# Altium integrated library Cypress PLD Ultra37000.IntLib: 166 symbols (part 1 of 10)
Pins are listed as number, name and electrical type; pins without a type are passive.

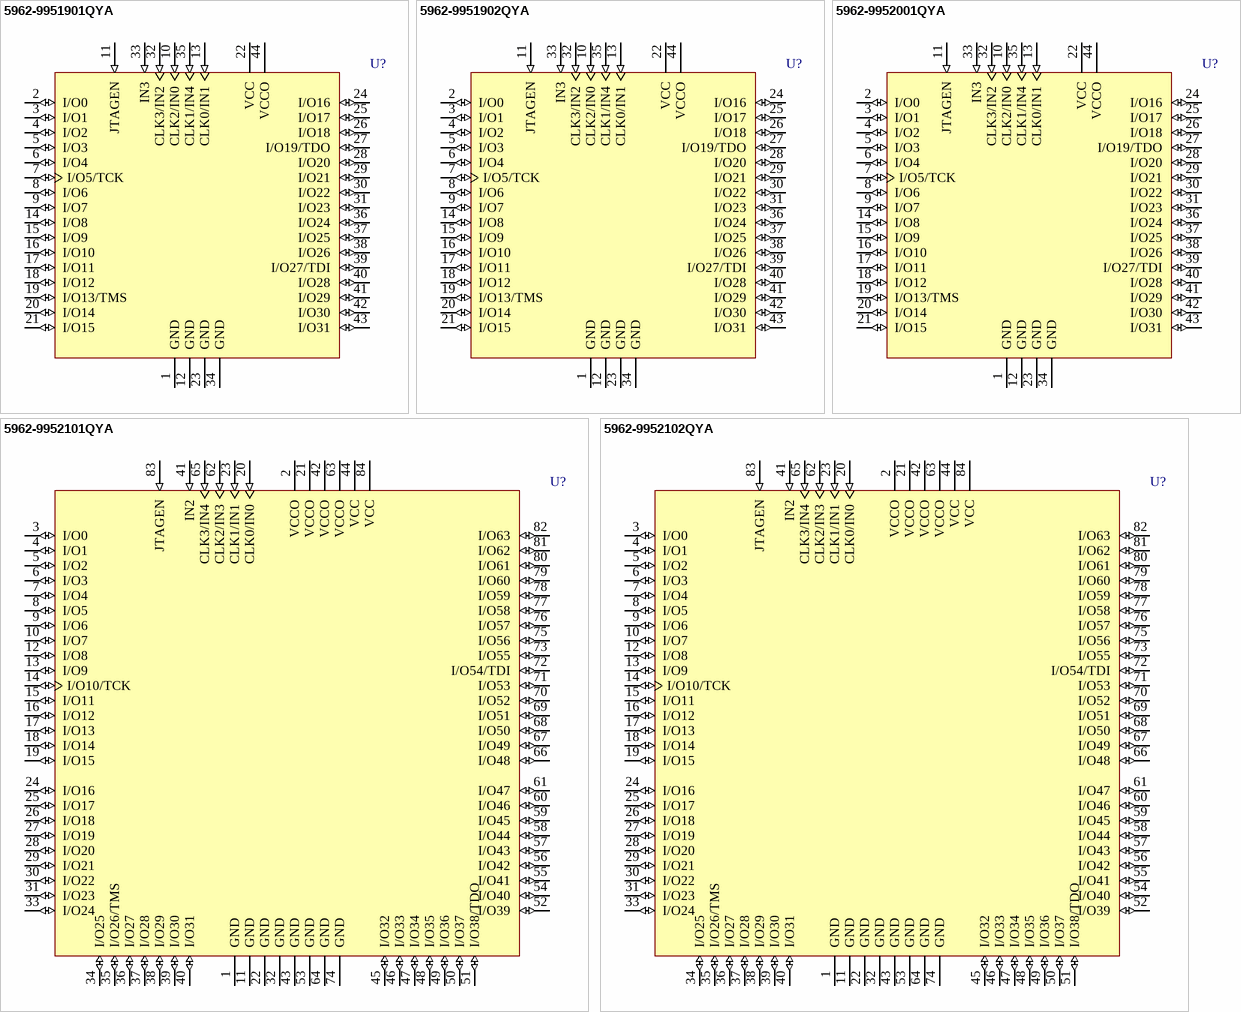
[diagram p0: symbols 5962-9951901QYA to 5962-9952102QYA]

## 5962-9951901QYA
designator U?
Ultra37000 5V, ISR High-Performance CPLD; Note: Component Name corresponds to Military Range
footprint Y67_N (Leaded Chip Carrier, 44-Leads, Body 16.5x16.5mm, Pitch 1.27mm, IPC Medium Density)
footprint Y67_L (Leaded Chip Carrier, 44-Leads, Body 16.5x16.5mm, Pitch 1.27mm, IPC High Density)
footprint Y67_M (Leaded Chip Carrier, 44-Leads, Body 16.5x16.5mm, Pitch 1.27mm, IPC Low Density)
3D model Y67 (44-Pin Ceramic Leaded Chip Carrier 1.27 mm Pitch)
pins: 1 GND (power), 2 I/O0 (io), 3 I/O1 (io), 4 I/O2 (io), 5 I/O3 (io), 6 I/O4 (io), 7 I/O5/TCK (io), 8 I/O6 (io), 9 I/O7 (io), 10 CLK2/IN0 (in), 11 JTAGEN (in), 12 GND (power), 13 CLK0/IN1 (in), 14 I/O8 (io), 15 I/O9 (io), 16 I/O10 (io), 17 I/O11 (io), 18 I/O12 (io), 19 I/O13/TMS (io), 20 I/O14 (io), 21 I/O15 (io), 22 VCC (power), 23 GND (power), 24 I/O16 (io), 25 I/O17 (io), 26 I/O18 (io), 27 I/O19/TDO (io), 28 I/O20 (io), 29 I/O21 (io), 30 I/O22 (io), 31 I/O23 (io), 32 CLK3/IN2 (in), 33 IN3 (in), 34 GND (power), 35 CLK1/IN4 (in), 36 I/O24 (io), 37 I/O25 (io), 38 I/O26 (io), 39 I/O27/TDI (io), 40 I/O28 (io), 41 I/O29 (io), 42 I/O30 (io), 43 I/O31 (io), 44 VCCO (power)

## 5962-9951902QYA
designator U?
Ultra37000 5V, ISR High-Performance CPLD; Note: Component Name corresponds to Military Range
footprint Y67_N (Leaded Chip Carrier, 44-Leads, Body 16.5x16.5mm, Pitch 1.27mm, IPC Medium Density)
footprint Y67_L (Leaded Chip Carrier, 44-Leads, Body 16.5x16.5mm, Pitch 1.27mm, IPC High Density)
footprint Y67_M (Leaded Chip Carrier, 44-Leads, Body 16.5x16.5mm, Pitch 1.27mm, IPC Low Density)
3D model Y67 (44-Pin Ceramic Leaded Chip Carrier 1.27 mm Pitch)
pins: 1 GND (power), 2 I/O0 (io), 3 I/O1 (io), 4 I/O2 (io), 5 I/O3 (io), 6 I/O4 (io), 7 I/O5/TCK (io), 8 I/O6 (io), 9 I/O7 (io), 10 CLK2/IN0 (in), 11 JTAGEN (in), 12 GND (power), 13 CLK0/IN1 (in), 14 I/O8 (io), 15 I/O9 (io), 16 I/O10 (io), 17 I/O11 (io), 18 I/O12 (io), 19 I/O13/TMS (io), 20 I/O14 (io), 21 I/O15 (io), 22 VCC (power), 23 GND (power), 24 I/O16 (io), 25 I/O17 (io), 26 I/O18 (io), 27 I/O19/TDO (io), 28 I/O20 (io), 29 I/O21 (io), 30 I/O22 (io), 31 I/O23 (io), 32 CLK3/IN2 (in), 33 IN3 (in), 34 GND (power), 35 CLK1/IN4 (in), 36 I/O24 (io), 37 I/O25 (io), 38 I/O26 (io), 39 I/O27/TDI (io), 40 I/O28 (io), 41 I/O29 (io), 42 I/O30 (io), 43 I/O31 (io), 44 VCCO (power)

## 5962-9952001QYA
designator U?
Ultra37000 3.3V, ISR High-Performance CPLD; Note: Component Name corresponds to Military Range
footprint Y67_N (Leaded Chip Carrier, 44-Leads, Body 16.5x16.5mm, Pitch 1.27mm, IPC Medium Density)
footprint Y67_L (Leaded Chip Carrier, 44-Leads, Body 16.5x16.5mm, Pitch 1.27mm, IPC High Density)
footprint Y67_M (Leaded Chip Carrier, 44-Leads, Body 16.5x16.5mm, Pitch 1.27mm, IPC Low Density)
3D model Y67 (44-Pin Ceramic Leaded Chip Carrier 1.27 mm Pitch)
pins: 1 GND (power), 2 I/O0 (io), 3 I/O1 (io), 4 I/O2 (io), 5 I/O3 (io), 6 I/O4 (io), 7 I/O5/TCK (io), 8 I/O6 (io), 9 I/O7 (io), 10 CLK2/IN0 (in), 11 JTAGEN (in), 12 GND (power), 13 CLK0/IN1 (in), 14 I/O8 (io), 15 I/O9 (io), 16 I/O10 (io), 17 I/O11 (io), 18 I/O12 (io), 19 I/O13/TMS (io), 20 I/O14 (io), 21 I/O15 (io), 22 VCC (power), 23 GND (power), 24 I/O16 (io), 25 I/O17 (io), 26 I/O18 (io), 27 I/O19/TDO (io), 28 I/O20 (io), 29 I/O21 (io), 30 I/O22 (io), 31 I/O23 (io), 32 CLK3/IN2 (in), 33 IN3 (in), 34 GND (power), 35 CLK1/IN4 (in), 36 I/O24 (io), 37 I/O25 (io), 38 I/O26 (io), 39 I/O27/TDI (io), 40 I/O28 (io), 41 I/O29 (io), 42 I/O30 (io), 43 I/O31 (io), 44 VCCO (power)

## 5962-9952101QYA
designator U?
Ultra37000 5V, ISR High-Performance CPLD; Note: Component Name corresponds to Military Range
footprint Y84_N (Leaded Chip Carrier, 84-Leads, Body 29.2x29.2mm, Pitch 1.27mm, IPC Medium Density)
footprint Y84_L (Leaded Chip Carrier, 84-Leads, Body 29.2x29.2mm, Pitch 1.27mm, IPC High Density)
footprint Y84_M (Leaded Chip Carrier, 84-Leads, Body 29.2x29.2mm, Pitch 1.27mm, IPC Low Density)
3D model Y84 (84-Pin Ceramic Leaded Chip Carrier 1.27 mm Pitch)
pins: 1 GND (power), 2 VCCO (power), 3 I/O0 (io), 4 I/O1 (io), 5 I/O2 (io), 6 I/O3 (io), 7 I/O4 (io), 8 I/O5 (io), 9 I/O6 (io), 10 I/O7 (io), 11 GND (power), 12 I/O8 (io), 13 I/O9 (io), 14 I/O10/TCK (io), 15 I/O11 (io), 16 I/O12 (io), 17 I/O13 (io), 18 I/O14 (io), 19 I/O15 (io), 20 CLK0/IN0 (in), 21 VCCO (power), 22 GND (power), 23 CLK1/IN1 (in), 24 I/O16 (io), 25 I/O17 (io), 26 I/O18 (io), 27 I/O19 (io), 28 I/O20 (io), 29 I/O21 (io), 30 I/O22 (io), 31 I/O23 (io), 32 GND (power), 33 I/O24 (io), 34 I/O25 (io), 35 I/O26/TMS (io), 36 I/O27 (io), 37 I/O28 (io), 38 I/O29 (io), 39 I/O30 (io), 40 I/O31 (io), 41 IN2 (in), 42 VCCO (power), 43 GND (power), 44 VCC (power), 45 I/O32 (io), 46 I/O33 (io), 47 I/O34 (io), 48 I/O35 (io), 49 I/O36 (io), 50 I/O37 (io), 51 I/O38/TDO (io), 52 I/O39 (io), 53 GND (power), 54 I/O40 (io), 55 I/O41 (io), 56 I/O42 (io), 57 I/O43 (io), 58 I/O44 (io), 59 I/O45 (io), 60 I/O46 (io), 61 I/O47 (io), 62 CLK2/IN3 (in), 63 VCCO (power), 64 GND (power), 65 CLK3/IN4 (in), 66 I/O48 (io), 67 I/O49 (io), 68 I/O50 (io), 69 I/O51 (io), 70 I/O52 (io), 71 I/O53 (io), 72 I/O54/TDI (io), 73 I/O55 (io), 74 GND (power), 75 I/O56 (io), 76 I/O57 (io), 77 I/O58 (io), 78 I/O59 (io), 79 I/O60 (io), 80 I/O61 (io), 81 I/O62 (io), 82 I/O63 (io), 83 JTAGEN (in), 84 VCC (power)

## 5962-9952102QYA
designator U?
Ultra37000 5V, ISR High-Performance CPLD; Note: Component Name corresponds to Military Range
footprint Y84_N (Leaded Chip Carrier, 84-Leads, Body 29.2x29.2mm, Pitch 1.27mm, IPC Medium Density)
footprint Y84_L (Leaded Chip Carrier, 84-Leads, Body 29.2x29.2mm, Pitch 1.27mm, IPC High Density)
footprint Y84_M (Leaded Chip Carrier, 84-Leads, Body 29.2x29.2mm, Pitch 1.27mm, IPC Low Density)
3D model Y84 (84-Pin Ceramic Leaded Chip Carrier 1.27 mm Pitch)
pins: 1 GND (power), 2 VCCO (power), 3 I/O0 (io), 4 I/O1 (io), 5 I/O2 (io), 6 I/O3 (io), 7 I/O4 (io), 8 I/O5 (io), 9 I/O6 (io), 10 I/O7 (io), 11 GND (power), 12 I/O8 (io), 13 I/O9 (io), 14 I/O10/TCK (io), 15 I/O11 (io), 16 I/O12 (io), 17 I/O13 (io), 18 I/O14 (io), 19 I/O15 (io), 20 CLK0/IN0 (in), 21 VCCO (power), 22 GND (power), 23 CLK1/IN1 (in), 24 I/O16 (io), 25 I/O17 (io), 26 I/O18 (io), 27 I/O19 (io), 28 I/O20 (io), 29 I/O21 (io), 30 I/O22 (io), 31 I/O23 (io), 32 GND (power), 33 I/O24 (io), 34 I/O25 (io), 35 I/O26/TMS (io), 36 I/O27 (io), 37 I/O28 (io), 38 I/O29 (io), 39 I/O30 (io), 40 I/O31 (io), 41 IN2 (in), 42 VCCO (power), 43 GND (power), 44 VCC (power), 45 I/O32 (io), 46 I/O33 (io), 47 I/O34 (io), 48 I/O35 (io), 49 I/O36 (io), 50 I/O37 (io), 51 I/O38/TDO (io), 52 I/O39 (io), 53 GND (power), 54 I/O40 (io), 55 I/O41 (io), 56 I/O42 (io), 57 I/O43 (io), 58 I/O44 (io), 59 I/O45 (io), 60 I/O46 (io), 61 I/O47 (io), 62 CLK2/IN3 (in), 63 VCCO (power), 64 GND (power), 65 CLK3/IN4 (in), 66 I/O48 (io), 67 I/O49 (io), 68 I/O50 (io), 69 I/O51 (io), 70 I/O52 (io), 71 I/O53 (io), 72 I/O54/TDI (io), 73 I/O55 (io), 74 GND (power), 75 I/O56 (io), 76 I/O57 (io), 77 I/O58 (io), 78 I/O59 (io), 79 I/O60 (io), 80 I/O61 (io), 81 I/O62 (io), 82 I/O63 (io), 83 JTAGEN (in), 84 VCC (power)

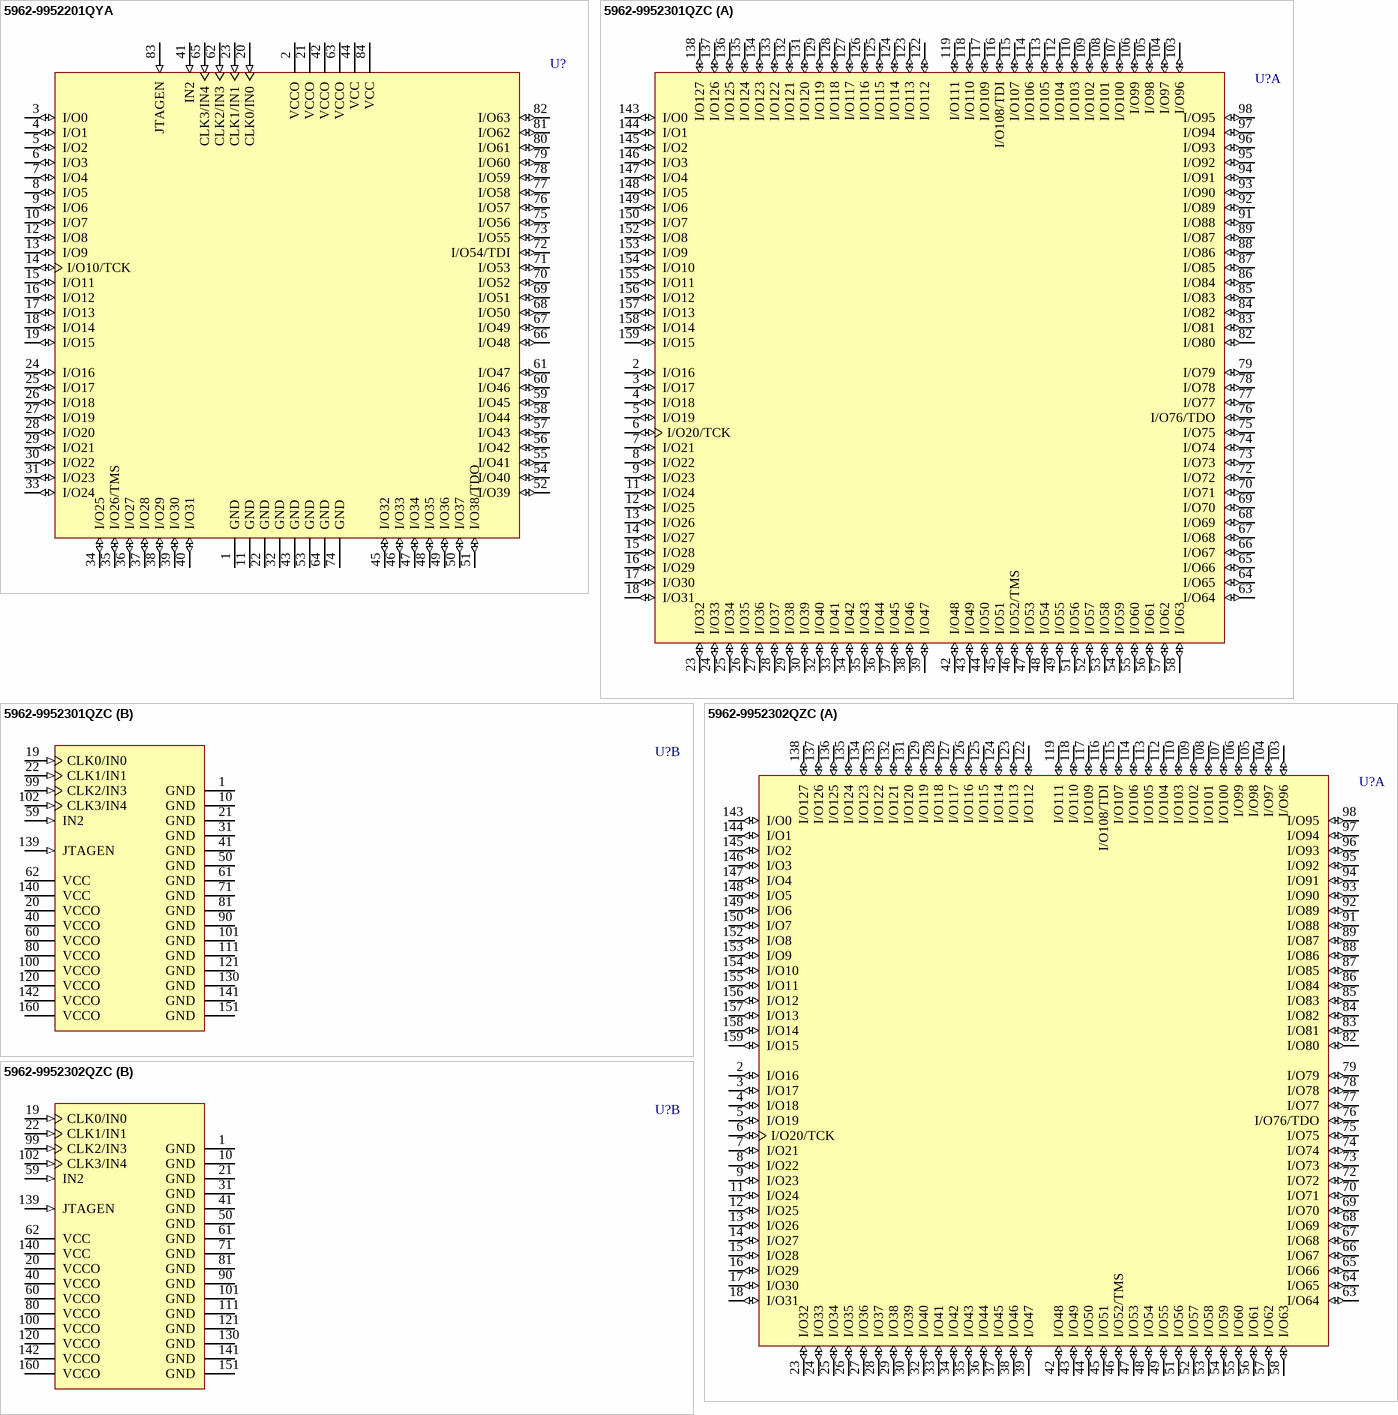
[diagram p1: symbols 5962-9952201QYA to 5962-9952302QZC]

## 5962-9952201QYA
designator U?
Ultra37000 3.3V, ISR High-Performance CPLD; Note: Component Name corresponds to Military Range
footprint Y84_N (Leaded Chip Carrier, 84-Leads, Body 29.2x29.2mm, Pitch 1.27mm, IPC Medium Density)
footprint Y84_L (Leaded Chip Carrier, 84-Leads, Body 29.2x29.2mm, Pitch 1.27mm, IPC High Density)
footprint Y84_M (Leaded Chip Carrier, 84-Leads, Body 29.2x29.2mm, Pitch 1.27mm, IPC Low Density)
3D model Y84 (84-Pin Ceramic Leaded Chip Carrier 1.27 mm Pitch)
pins: 1 GND (power), 2 VCCO (power), 3 I/O0 (io), 4 I/O1 (io), 5 I/O2 (io), 6 I/O3 (io), 7 I/O4 (io), 8 I/O5 (io), 9 I/O6 (io), 10 I/O7 (io), 11 GND (power), 12 I/O8 (io), 13 I/O9 (io), 14 I/O10/TCK (io), 15 I/O11 (io), 16 I/O12 (io), 17 I/O13 (io), 18 I/O14 (io), 19 I/O15 (io), 20 CLK0/IN0 (in), 21 VCCO (power), 22 GND (power), 23 CLK1/IN1 (in), 24 I/O16 (io), 25 I/O17 (io), 26 I/O18 (io), 27 I/O19 (io), 28 I/O20 (io), 29 I/O21 (io), 30 I/O22 (io), 31 I/O23 (io), 32 GND (power), 33 I/O24 (io), 34 I/O25 (io), 35 I/O26/TMS (io), 36 I/O27 (io), 37 I/O28 (io), 38 I/O29 (io), 39 I/O30 (io), 40 I/O31 (io), 41 IN2 (in), 42 VCCO (power), 43 GND (power), 44 VCC (power), 45 I/O32 (io), 46 I/O33 (io), 47 I/O34 (io), 48 I/O35 (io), 49 I/O36 (io), 50 I/O37 (io), 51 I/O38/TDO (io), 52 I/O39 (io), 53 GND (power), 54 I/O40 (io), 55 I/O41 (io), 56 I/O42 (io), 57 I/O43 (io), 58 I/O44 (io), 59 I/O45 (io), 60 I/O46 (io), 61 I/O47 (io), 62 CLK2/IN3 (in), 63 VCCO (power), 64 GND (power), 65 CLK3/IN4 (in), 66 I/O48 (io), 67 I/O49 (io), 68 I/O50 (io), 69 I/O51 (io), 70 I/O52 (io), 71 I/O53 (io), 72 I/O54/TDI (io), 73 I/O55 (io), 74 GND (power), 75 I/O56 (io), 76 I/O57 (io), 77 I/O58 (io), 78 I/O59 (io), 79 I/O60 (io), 80 I/O61 (io), 81 I/O62 (io), 82 I/O63 (io), 83 JTAGEN (in), 84 VCC (power)

## 5962-9952301QZC
designator U?
Ultra37000 5V, ISR High-Performance CPLD; Note: Component Name corresponds to Military Range
footprint U162_N (QFP, 160-Leads, Body 28 x 28mm, Pitch 0.65mm, IPC Medium Density)
footprint U162_L (QFP, 160-Leads, Body 28 x 28mm, Pitch 0.65mm, IPC High Density)
footprint U162_M (QFP, 160-Leads, Body 28 x 28mm, Pitch 0.65mm, IPC Low Density)
3D model U162 (160-Pin Ceramic Cavity Up Quad Flat Pack 0.65 mm Pitch)
part A pins: 2 I/O16 (io), 3 I/O17 (io), 4 I/O18 (io), 5 I/O19 (io), 6 I/O20/TCK (io), 7 I/O21 (io), 8 I/O22 (io), 9 I/O23 (io), 11 I/O24 (io), 12 I/O25 (io), 13 I/O26 (io), 14 I/O27 (io), 15 I/O28 (io), 16 I/O29 (io), 17 I/O30 (io), 18 I/O31 (io), 23 I/O32 (io), 24 I/O33 (io), 25 I/O34 (io), 26 I/O35 (io), 27 I/O36 (io), 28 I/O37 (io), 29 I/O38 (io), 30 I/O39 (io), 32 I/O40 (io), 33 I/O41 (io), 34 I/O42 (io), 35 I/O43 (io), 36 I/O44 (io), 37 I/O45 (io), 38 I/O46 (io), 39 I/O47 (io), 42 I/O48 (io), 43 I/O49 (io), 44 I/O50 (io), 45 I/O51 (io), 46 I/O52/TMS (io), 47 I/O53 (io), 48 I/O54 (io), 49 I/O55 (io), 51 I/O56 (io), 52 I/O57 (io), 53 I/O58 (io), 54 I/O59 (io), 55 I/O60 (io), 56 I/O61 (io), 57 I/O62 (io), 58 I/O63 (io), 63 I/O64 (io), 64 I/O65 (io), 65 I/O66 (io), 66 I/O67 (io), 67 I/O68 (io), 68 I/O69 (io), 69 I/O70 (io), 70 I/O71 (io), 72 I/O72 (io), 73 I/O73 (io), 74 I/O74 (io), 75 I/O75 (io), 76 I/O76/TDO (io), 77 I/O77 (io), 78 I/O78 (io), 79 I/O79 (io), 82 I/O80 (io), 83 I/O81 (io), 84 I/O82 (io), 85 I/O83 (io), 86 I/O84 (io), 87 I/O85 (io), 88 I/O86 (io), 89 I/O87 (io), 91 I/O88 (io), 92 I/O89 (io), 93 I/O90 (io), 94 I/O91 (io), 95 I/O92 (io), 96 I/O93 (io), 97 I/O94 (io), 98 I/O95 (io), 103 I/O96 (io), 104 I/O97 (io), 105 I/O98 (io), 106 I/O99 (io), 107 I/O100 (io), 108 I/O101 (io), 109 I/O102 (io), 110 I/O103 (io), 112 I/O104 (io), 113 I/O105 (io), 114 I/O106 (io), 115 I/O107 (io), 116 I/O108/TDI (io), 117 I/O109 (io), 118 I/O110 (io), 119 I/O111 (io), 122 I/O112 (io), 123 I/O113 (io), 124 I/O114 (io), 125 I/O115 (io), 126 I/O116 (io), 127 I/O117 (io), 128 I/O118 (io), 129 I/O119 (io), 131 I/O120 (io), 132 I/O121 (io), 133 I/O122 (io), 134 I/O123 (io), 135 I/O124 (io), 136 I/O125 (io), 137 I/O126 (io), 138 I/O127 (io), 143 I/O0 (io), 144 I/O1 (io), 145 I/O2 (io), 146 I/O3 (io), 147 I/O4 (io), 148 I/O5 (io), 149 I/O6 (io), 150 I/O7 (io), 152 I/O8 (io), 153 I/O9 (io), 154 I/O10 (io), 155 I/O11 (io), 156 I/O12 (io), 157 I/O13 (io), 158 I/O14 (io), 159 I/O15 (io)
part B pins: 1 GND (power), 10 GND (power), 19 CLK0/IN0 (in), 20 VCCO (power), 21 GND (power), 22 CLK1/IN1 (in), 31 GND (power), 40 VCCO (power), 41 GND (power), 50 GND (power), 59 IN2 (in), 60 VCCO (power), 61 GND (power), 62 VCC (power), 71 GND (power), 80 VCCO (power), 81 GND (power), 90 GND (power), 99 CLK2/IN3 (in), 100 VCCO (power), 101 GND (power), 102 CLK3/IN4 (in), 111 GND (power), 120 VCCO (power), 121 GND (power), 130 GND (power), 139 JTAGEN (in), 140 VCC (power), 141 GND (power), 142 VCCO (power), 151 GND (power), 160 VCCO (power)

## 5962-9952302QZC
designator U?
Ultra37000 5V, ISR High-Performance CPLD; Note: Component Name corresponds to Military Range
footprint U162_N (QFP, 160-Leads, Body 28 x 28mm, Pitch 0.65mm, IPC Medium Density)
footprint U162_L (QFP, 160-Leads, Body 28 x 28mm, Pitch 0.65mm, IPC High Density)
footprint U162_M (QFP, 160-Leads, Body 28 x 28mm, Pitch 0.65mm, IPC Low Density)
3D model U162 (160-Pin Ceramic Cavity Up Quad Flat Pack 0.65 mm Pitch)
part A pins: 2 I/O16 (io), 3 I/O17 (io), 4 I/O18 (io), 5 I/O19 (io), 6 I/O20/TCK (io), 7 I/O21 (io), 8 I/O22 (io), 9 I/O23 (io), 11 I/O24 (io), 12 I/O25 (io), 13 I/O26 (io), 14 I/O27 (io), 15 I/O28 (io), 16 I/O29 (io), 17 I/O30 (io), 18 I/O31 (io), 23 I/O32 (io), 24 I/O33 (io), 25 I/O34 (io), 26 I/O35 (io), 27 I/O36 (io), 28 I/O37 (io), 29 I/O38 (io), 30 I/O39 (io), 32 I/O40 (io), 33 I/O41 (io), 34 I/O42 (io), 35 I/O43 (io), 36 I/O44 (io), 37 I/O45 (io), 38 I/O46 (io), 39 I/O47 (io), 42 I/O48 (io), 43 I/O49 (io), 44 I/O50 (io), 45 I/O51 (io), 46 I/O52/TMS (io), 47 I/O53 (io), 48 I/O54 (io), 49 I/O55 (io), 51 I/O56 (io), 52 I/O57 (io), 53 I/O58 (io), 54 I/O59 (io), 55 I/O60 (io), 56 I/O61 (io), 57 I/O62 (io), 58 I/O63 (io), 63 I/O64 (io), 64 I/O65 (io), 65 I/O66 (io), 66 I/O67 (io), 67 I/O68 (io), 68 I/O69 (io), 69 I/O70 (io), 70 I/O71 (io), 72 I/O72 (io), 73 I/O73 (io), 74 I/O74 (io), 75 I/O75 (io), 76 I/O76/TDO (io), 77 I/O77 (io), 78 I/O78 (io), 79 I/O79 (io), 82 I/O80 (io), 83 I/O81 (io), 84 I/O82 (io), 85 I/O83 (io), 86 I/O84 (io), 87 I/O85 (io), 88 I/O86 (io), 89 I/O87 (io), 91 I/O88 (io), 92 I/O89 (io), 93 I/O90 (io), 94 I/O91 (io), 95 I/O92 (io), 96 I/O93 (io), 97 I/O94 (io), 98 I/O95 (io), 103 I/O96 (io), 104 I/O97 (io), 105 I/O98 (io), 106 I/O99 (io), 107 I/O100 (io), 108 I/O101 (io), 109 I/O102 (io), 110 I/O103 (io), 112 I/O104 (io), 113 I/O105 (io), 114 I/O106 (io), 115 I/O107 (io), 116 I/O108/TDI (io), 117 I/O109 (io), 118 I/O110 (io), 119 I/O111 (io), 122 I/O112 (io), 123 I/O113 (io), 124 I/O114 (io), 125 I/O115 (io), 126 I/O116 (io), 127 I/O117 (io), 128 I/O118 (io), 129 I/O119 (io), 131 I/O120 (io), 132 I/O121 (io), 133 I/O122 (io), 134 I/O123 (io), 135 I/O124 (io), 136 I/O125 (io), 137 I/O126 (io), 138 I/O127 (io), 143 I/O0 (io), 144 I/O1 (io), 145 I/O2 (io), 146 I/O3 (io), 147 I/O4 (io), 148 I/O5 (io), 149 I/O6 (io), 150 I/O7 (io), 152 I/O8 (io), 153 I/O9 (io), 154 I/O10 (io), 155 I/O11 (io), 156 I/O12 (io), 157 I/O13 (io), 158 I/O14 (io), 159 I/O15 (io)
part B pins: 1 GND (power), 10 GND (power), 19 CLK0/IN0 (in), 20 VCCO (power), 21 GND (power), 22 CLK1/IN1 (in), 31 GND (power), 40 VCCO (power), 41 GND (power), 50 GND (power), 59 IN2 (in), 60 VCCO (power), 61 GND (power), 62 VCC (power), 71 GND (power), 80 VCCO (power), 81 GND (power), 90 GND (power), 99 CLK2/IN3 (in), 100 VCCO (power), 101 GND (power), 102 CLK3/IN4 (in), 111 GND (power), 120 VCCO (power), 121 GND (power), 130 GND (power), 139 JTAGEN (in), 140 VCC (power), 141 GND (power), 142 VCCO (power), 151 GND (power), 160 VCCO (power)

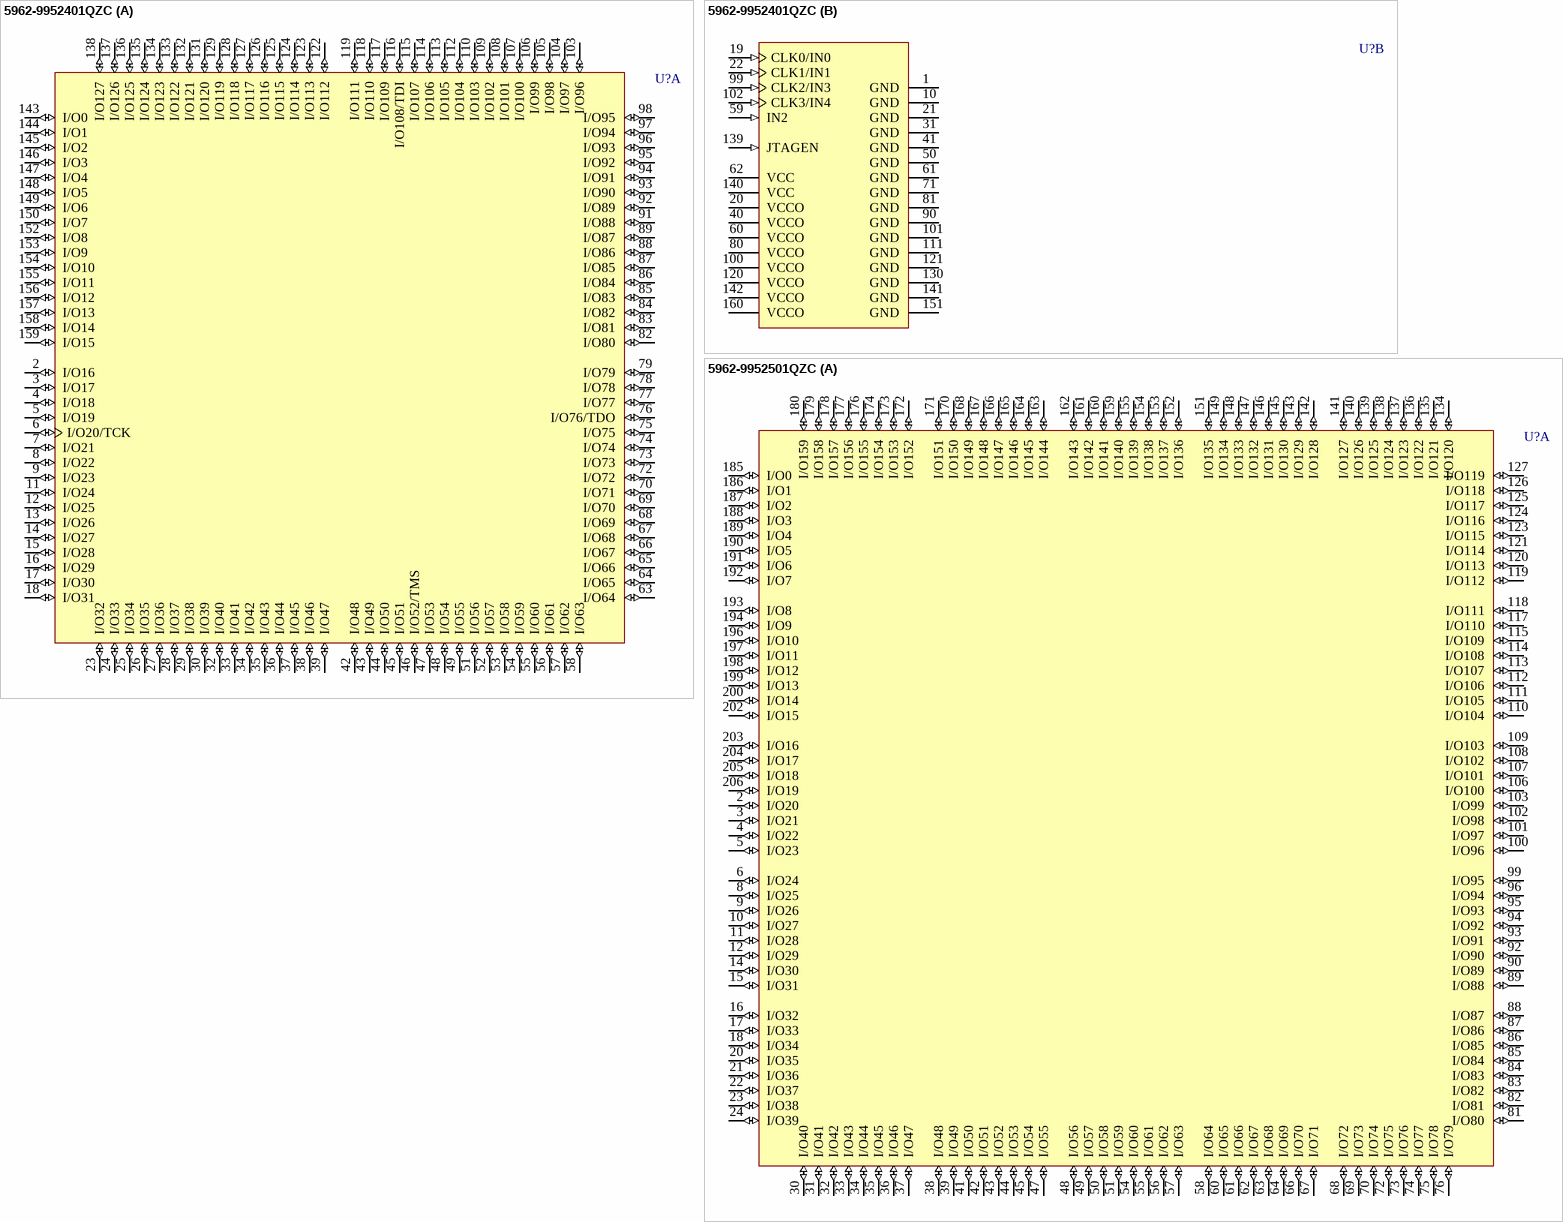
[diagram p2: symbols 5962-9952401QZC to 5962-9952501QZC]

## 5962-9952401QZC
designator U?
Ultra37000 3.3V, ISR High-Performance CPLD; Note: Component Name corresponds to Military Range
footprint U162_N (QFP, 160-Leads, Body 28 x 28mm, Pitch 0.65mm, IPC Medium Density)
footprint U162_L (QFP, 160-Leads, Body 28 x 28mm, Pitch 0.65mm, IPC High Density)
footprint U162_M (QFP, 160-Leads, Body 28 x 28mm, Pitch 0.65mm, IPC Low Density)
3D model U162 (160-Pin Ceramic Cavity Up Quad Flat Pack 0.65 mm Pitch)
part A pins: 2 I/O16 (io), 3 I/O17 (io), 4 I/O18 (io), 5 I/O19 (io), 6 I/O20/TCK (io), 7 I/O21 (io), 8 I/O22 (io), 9 I/O23 (io), 11 I/O24 (io), 12 I/O25 (io), 13 I/O26 (io), 14 I/O27 (io), 15 I/O28 (io), 16 I/O29 (io), 17 I/O30 (io), 18 I/O31 (io), 23 I/O32 (io), 24 I/O33 (io), 25 I/O34 (io), 26 I/O35 (io), 27 I/O36 (io), 28 I/O37 (io), 29 I/O38 (io), 30 I/O39 (io), 32 I/O40 (io), 33 I/O41 (io), 34 I/O42 (io), 35 I/O43 (io), 36 I/O44 (io), 37 I/O45 (io), 38 I/O46 (io), 39 I/O47 (io), 42 I/O48 (io), 43 I/O49 (io), 44 I/O50 (io), 45 I/O51 (io), 46 I/O52/TMS (io), 47 I/O53 (io), 48 I/O54 (io), 49 I/O55 (io), 51 I/O56 (io), 52 I/O57 (io), 53 I/O58 (io), 54 I/O59 (io), 55 I/O60 (io), 56 I/O61 (io), 57 I/O62 (io), 58 I/O63 (io), 63 I/O64 (io), 64 I/O65 (io), 65 I/O66 (io), 66 I/O67 (io), 67 I/O68 (io), 68 I/O69 (io), 69 I/O70 (io), 70 I/O71 (io), 72 I/O72 (io), 73 I/O73 (io), 74 I/O74 (io), 75 I/O75 (io), 76 I/O76/TDO (io), 77 I/O77 (io), 78 I/O78 (io), 79 I/O79 (io), 82 I/O80 (io), 83 I/O81 (io), 84 I/O82 (io), 85 I/O83 (io), 86 I/O84 (io), 87 I/O85 (io), 88 I/O86 (io), 89 I/O87 (io), 91 I/O88 (io), 92 I/O89 (io), 93 I/O90 (io), 94 I/O91 (io), 95 I/O92 (io), 96 I/O93 (io), 97 I/O94 (io), 98 I/O95 (io), 103 I/O96 (io), 104 I/O97 (io), 105 I/O98 (io), 106 I/O99 (io), 107 I/O100 (io), 108 I/O101 (io), 109 I/O102 (io), 110 I/O103 (io), 112 I/O104 (io), 113 I/O105 (io), 114 I/O106 (io), 115 I/O107 (io), 116 I/O108/TDI (io), 117 I/O109 (io), 118 I/O110 (io), 119 I/O111 (io), 122 I/O112 (io), 123 I/O113 (io), 124 I/O114 (io), 125 I/O115 (io), 126 I/O116 (io), 127 I/O117 (io), 128 I/O118 (io), 129 I/O119 (io), 131 I/O120 (io), 132 I/O121 (io), 133 I/O122 (io), 134 I/O123 (io), 135 I/O124 (io), 136 I/O125 (io), 137 I/O126 (io), 138 I/O127 (io), 143 I/O0 (io), 144 I/O1 (io), 145 I/O2 (io), 146 I/O3 (io), 147 I/O4 (io), 148 I/O5 (io), 149 I/O6 (io), 150 I/O7 (io), 152 I/O8 (io), 153 I/O9 (io), 154 I/O10 (io), 155 I/O11 (io), 156 I/O12 (io), 157 I/O13 (io), 158 I/O14 (io), 159 I/O15 (io)
part B pins: 1 GND (power), 10 GND (power), 19 CLK0/IN0 (in), 20 VCCO (power), 21 GND (power), 22 CLK1/IN1 (in), 31 GND (power), 40 VCCO (power), 41 GND (power), 50 GND (power), 59 IN2 (in), 60 VCCO (power), 61 GND (power), 62 VCC (power), 71 GND (power), 80 VCCO (power), 81 GND (power), 90 GND (power), 99 CLK2/IN3 (in), 100 VCCO (power), 101 GND (power), 102 CLK3/IN4 (in), 111 GND (power), 120 VCCO (power), 121 GND (power), 130 GND (power), 139 JTAGEN (in), 140 VCC (power), 141 GND (power), 142 VCCO (power), 151 GND (power), 160 VCCO (power)

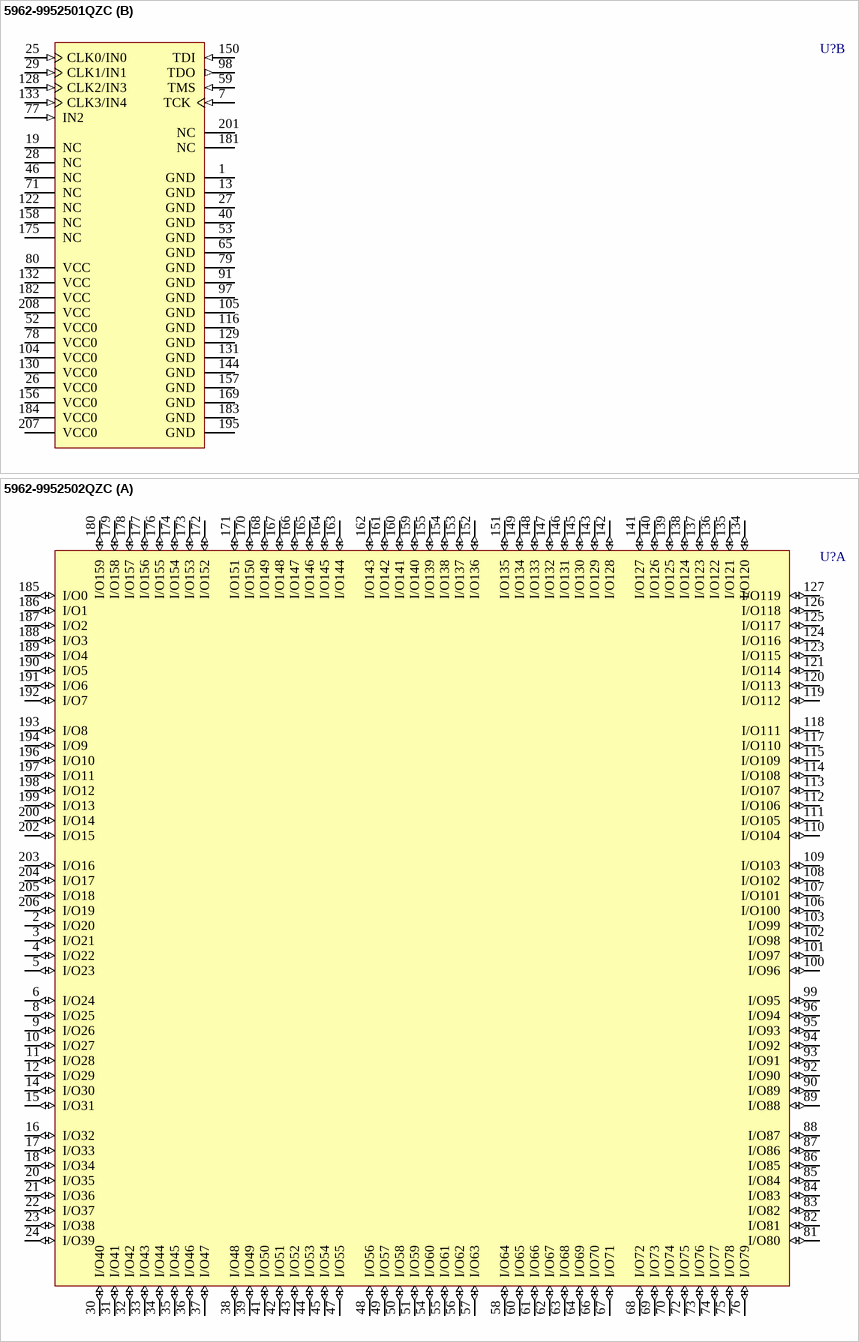
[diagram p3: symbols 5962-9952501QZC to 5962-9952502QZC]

## 5962-9952501QZC
designator U?
Ultra37000 5V, ISR High-Performance CPLD; Note: Component Name corresponds to Military Range
footprint U208_N (Shrink QFP, 208-Leads, Body 28x28mm, Pitch 0.5mm, IPC Medium Density)
footprint U208_L (Shrink QFP, 208-Leads, Body 28x28mm, Pitch 0.5mm, IPC High Density)
footprint U208_M (Shrink QFP, 208-Leads, Body 28x28mm, Pitch 0.5mm, IPC Low Density)
3D model U208 (208-Pin Ceramic Cavity Up Shrink Quad Flat Pack 0.5 mm Pitch)
part A pins: 2 I/O20 (io), 3 I/O21 (io), 4 I/O22 (io), 5 I/O23 (io), 6 I/O24 (io), 8 I/O25 (io), 9 I/O26 (io), 10 I/O27 (io), 11 I/O28 (io), 12 I/O29 (io), 14 I/O30 (io), 15 I/O31 (io), 16 I/O32 (io), 17 I/O33 (io), 18 I/O34 (io), 20 I/O35 (io), 21 I/O36 (io), 22 I/O37 (io), 23 I/O38 (io), 24 I/O39 (io), 30 I/O40 (io), 31 I/O41 (io), 32 I/O42 (io), 33 I/O43 (io), 34 I/O44 (io), 35 I/O45 (io), 36 I/O46 (io), 37 I/O47 (io), 38 I/O48 (io), 39 I/O49 (io), 41 I/O50 (io), 42 I/O51 (io), 43 I/O52 (io), 44 I/O53 (io), 45 I/O54 (io), 47 I/O55 (io), 48 I/O56 (io), 49 I/O57 (io), 50 I/O58 (io), 51 I/O59 (io), 54 I/O60 (io), 55 I/O61 (io), 56 I/O62 (io), 57 I/O63 (io), 58 I/O64 (io), 60 I/O65 (io), 61 I/O66 (io), 62 I/O67 (io), 63 I/O68 (io), 64 I/O69 (io), 66 I/O70 (io), 67 I/O71 (io), 68 I/O72 (io), 69 I/O73 (io), 70 I/O74 (io), 72 I/O75 (io), 73 I/O76 (io), 74 I/O77 (io), 75 I/O78 (io), 76 I/O79 (io), 81 I/O80 (io), 82 I/O81 (io), 83 I/O82 (io), 84 I/O83 (io), 85 I/O84 (io), 86 I/O85 (io), 87 I/O86 (io), 88 I/O87 (io), 89 I/O88 (io), 90 I/O89 (io), 92 I/O90 (io), 93 I/O91 (io), 94 I/O92 (io), 95 I/O93 (io), 96 I/O94 (io), 99 I/O95 (io), 100 I/O96 (io), 101 I/O97 (io), 102 I/O98 (io), 103 I/O99 (io), 106 I/O100 (io), 107 I/O101 (io), 108 I/O102 (io), 109 I/O103 (io), 110 I/O104 (io), 111 I/O105 (io), 112 I/O106 (io), 113 I/O107 (io), 114 I/O108 (io), 115 I/O109 (io), 117 I/O110 (io), 118 I/O111 (io), 119 I/O112 (io), 120 I/O113 (io), 121 I/O114 (io), 123 I/O115 (io), 124 I/O116 (io), 125 I/O117 (io), 126 I/O118 (io), 127 I/O119 (io), 134 I/O120 (io), 135 I/O121 (io), 136 I/O122 (io), 137 I/O123 (io), 138 I/O124 (io), 139 I/O125 (io), 140 I/O126 (io), 141 I/O127 (io), 142 I/O128 (io), 143 I/O129 (io), 145 I/O130 (io), 146 I/O131 (io), 147 I/O132 (io), 148 I/O133 (io), 149 I/O134 (io), 151 I/O135 (io), 152 I/O136 (io), 153 I/O137 (io), 154 I/O138 (io), 155 I/O139 (io), 159 I/O140 (io), 160 I/O141 (io), 161 I/O142 (io), 162 I/O143 (io), 163 I/O144 (io), 164 I/O145 (io), 165 I/O146 (io), 166 I/O147 (io), 167 I/O148 (io), 168 I/O149 (io), 170 I/O150 (io), 171 I/O151 (io), 172 I/O152 (io), 173 I/O153 (io), 174 I/O154 (io), 176 I/O155 (io), 177 I/O156 (io), 178 I/O157 (io), 179 I/O158 (io), 180 I/O159 (io), 185 I/O0 (io), 186 I/O1 (io), 187 I/O2 (io), 188 I/O3 (io), 189 I/O4 (io), 190 I/O5 (io), 191 I/O6 (io), 192 I/O7 (io), 193 I/O8 (io), 194 I/O9 (io), 196 I/O10 (io), 197 I/O11 (io), 198 I/O12 (io), 199 I/O13 (io), 200 I/O14 (io), 202 I/O15 (io), 203 I/O16 (io), 204 I/O17 (io), 205 I/O18 (io), 206 I/O19 (io)
part B pins: 1 GND (power), 7 TCK (in), 13 GND (power), 19 NC, 25 CLK0/IN0 (in), 26 VCC0 (power), 27 GND (power), 28 NC, 29 CLK1/IN1 (in), 40 GND (power), 46 NC, 52 VCC0 (power), 53 GND (power), 59 TMS (in), 65 GND (power), 71 NC, 77 IN2 (in), 78 VCC0 (power), 79 GND (power), 80 VCC (power), 91 GND (power), 97 GND (power), 98 TDO (out), 104 VCC0 (power), 105 GND (power), 116 GND (power), 122 NC, 128 CLK2/IN3 (in), 129 GND (power), 130 VCC0 (power), 131 GND (power), 132 VCC (power), 133 CLK3/IN4 (in), 144 GND (power), 150 TDI (in), 156 VCC0 (power), 157 GND (power), 158 NC, 169 GND (power), 175 NC, 181 NC, 182 VCC (power), 183 GND (power), 184 VCC0 (power), 195 GND (power), 201 NC, 207 VCC0 (power), 208 VCC (power)

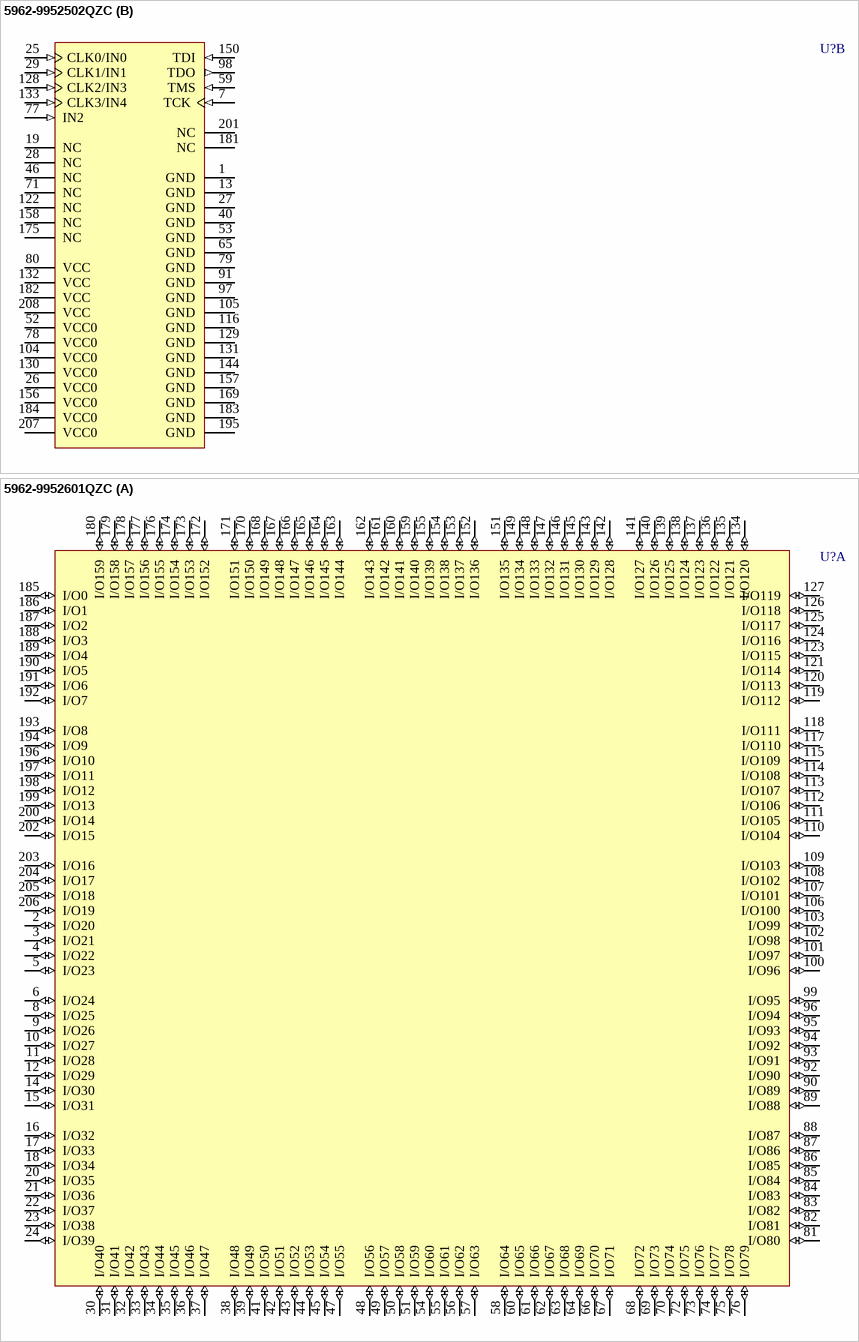
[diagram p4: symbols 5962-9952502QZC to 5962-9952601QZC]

## 5962-9952502QZC
designator U?
Ultra37000 5V, ISR High-Performance CPLD; Note: Component Name corresponds to Military Range
footprint U208_N (Shrink QFP, 208-Leads, Body 28x28mm, Pitch 0.5mm, IPC Medium Density)
footprint U208_L (Shrink QFP, 208-Leads, Body 28x28mm, Pitch 0.5mm, IPC High Density)
footprint U208_M (Shrink QFP, 208-Leads, Body 28x28mm, Pitch 0.5mm, IPC Low Density)
3D model U208 (208-Pin Ceramic Cavity Up Shrink Quad Flat Pack 0.5 mm Pitch)
part A pins: 2 I/O20 (io), 3 I/O21 (io), 4 I/O22 (io), 5 I/O23 (io), 6 I/O24 (io), 8 I/O25 (io), 9 I/O26 (io), 10 I/O27 (io), 11 I/O28 (io), 12 I/O29 (io), 14 I/O30 (io), 15 I/O31 (io), 16 I/O32 (io), 17 I/O33 (io), 18 I/O34 (io), 20 I/O35 (io), 21 I/O36 (io), 22 I/O37 (io), 23 I/O38 (io), 24 I/O39 (io), 30 I/O40 (io), 31 I/O41 (io), 32 I/O42 (io), 33 I/O43 (io), 34 I/O44 (io), 35 I/O45 (io), 36 I/O46 (io), 37 I/O47 (io), 38 I/O48 (io), 39 I/O49 (io), 41 I/O50 (io), 42 I/O51 (io), 43 I/O52 (io), 44 I/O53 (io), 45 I/O54 (io), 47 I/O55 (io), 48 I/O56 (io), 49 I/O57 (io), 50 I/O58 (io), 51 I/O59 (io), 54 I/O60 (io), 55 I/O61 (io), 56 I/O62 (io), 57 I/O63 (io), 58 I/O64 (io), 60 I/O65 (io), 61 I/O66 (io), 62 I/O67 (io), 63 I/O68 (io), 64 I/O69 (io), 66 I/O70 (io), 67 I/O71 (io), 68 I/O72 (io), 69 I/O73 (io), 70 I/O74 (io), 72 I/O75 (io), 73 I/O76 (io), 74 I/O77 (io), 75 I/O78 (io), 76 I/O79 (io), 81 I/O80 (io), 82 I/O81 (io), 83 I/O82 (io), 84 I/O83 (io), 85 I/O84 (io), 86 I/O85 (io), 87 I/O86 (io), 88 I/O87 (io), 89 I/O88 (io), 90 I/O89 (io), 92 I/O90 (io), 93 I/O91 (io), 94 I/O92 (io), 95 I/O93 (io), 96 I/O94 (io), 99 I/O95 (io), 100 I/O96 (io), 101 I/O97 (io), 102 I/O98 (io), 103 I/O99 (io), 106 I/O100 (io), 107 I/O101 (io), 108 I/O102 (io), 109 I/O103 (io), 110 I/O104 (io), 111 I/O105 (io), 112 I/O106 (io), 113 I/O107 (io), 114 I/O108 (io), 115 I/O109 (io), 117 I/O110 (io), 118 I/O111 (io), 119 I/O112 (io), 120 I/O113 (io), 121 I/O114 (io), 123 I/O115 (io), 124 I/O116 (io), 125 I/O117 (io), 126 I/O118 (io), 127 I/O119 (io), 134 I/O120 (io), 135 I/O121 (io), 136 I/O122 (io), 137 I/O123 (io), 138 I/O124 (io), 139 I/O125 (io), 140 I/O126 (io), 141 I/O127 (io), 142 I/O128 (io), 143 I/O129 (io), 145 I/O130 (io), 146 I/O131 (io), 147 I/O132 (io), 148 I/O133 (io), 149 I/O134 (io), 151 I/O135 (io), 152 I/O136 (io), 153 I/O137 (io), 154 I/O138 (io), 155 I/O139 (io), 159 I/O140 (io), 160 I/O141 (io), 161 I/O142 (io), 162 I/O143 (io), 163 I/O144 (io), 164 I/O145 (io), 165 I/O146 (io), 166 I/O147 (io), 167 I/O148 (io), 168 I/O149 (io), 170 I/O150 (io), 171 I/O151 (io), 172 I/O152 (io), 173 I/O153 (io), 174 I/O154 (io), 176 I/O155 (io), 177 I/O156 (io), 178 I/O157 (io), 179 I/O158 (io), 180 I/O159 (io), 185 I/O0 (io), 186 I/O1 (io), 187 I/O2 (io), 188 I/O3 (io), 189 I/O4 (io), 190 I/O5 (io), 191 I/O6 (io), 192 I/O7 (io), 193 I/O8 (io), 194 I/O9 (io), 196 I/O10 (io), 197 I/O11 (io), 198 I/O12 (io), 199 I/O13 (io), 200 I/O14 (io), 202 I/O15 (io), 203 I/O16 (io), 204 I/O17 (io), 205 I/O18 (io), 206 I/O19 (io)
part B pins: 1 GND (power), 7 TCK (in), 13 GND (power), 19 NC, 25 CLK0/IN0 (in), 26 VCC0 (power), 27 GND (power), 28 NC, 29 CLK1/IN1 (in), 40 GND (power), 46 NC, 52 VCC0 (power), 53 GND (power), 59 TMS (in), 65 GND (power), 71 NC, 77 IN2 (in), 78 VCC0 (power), 79 GND (power), 80 VCC (power), 91 GND (power), 97 GND (power), 98 TDO (out), 104 VCC0 (power), 105 GND (power), 116 GND (power), 122 NC, 128 CLK2/IN3 (in), 129 GND (power), 130 VCC0 (power), 131 GND (power), 132 VCC (power), 133 CLK3/IN4 (in), 144 GND (power), 150 TDI (in), 156 VCC0 (power), 157 GND (power), 158 NC, 169 GND (power), 175 NC, 181 NC, 182 VCC (power), 183 GND (power), 184 VCC0 (power), 195 GND (power), 201 NC, 207 VCC0 (power), 208 VCC (power)

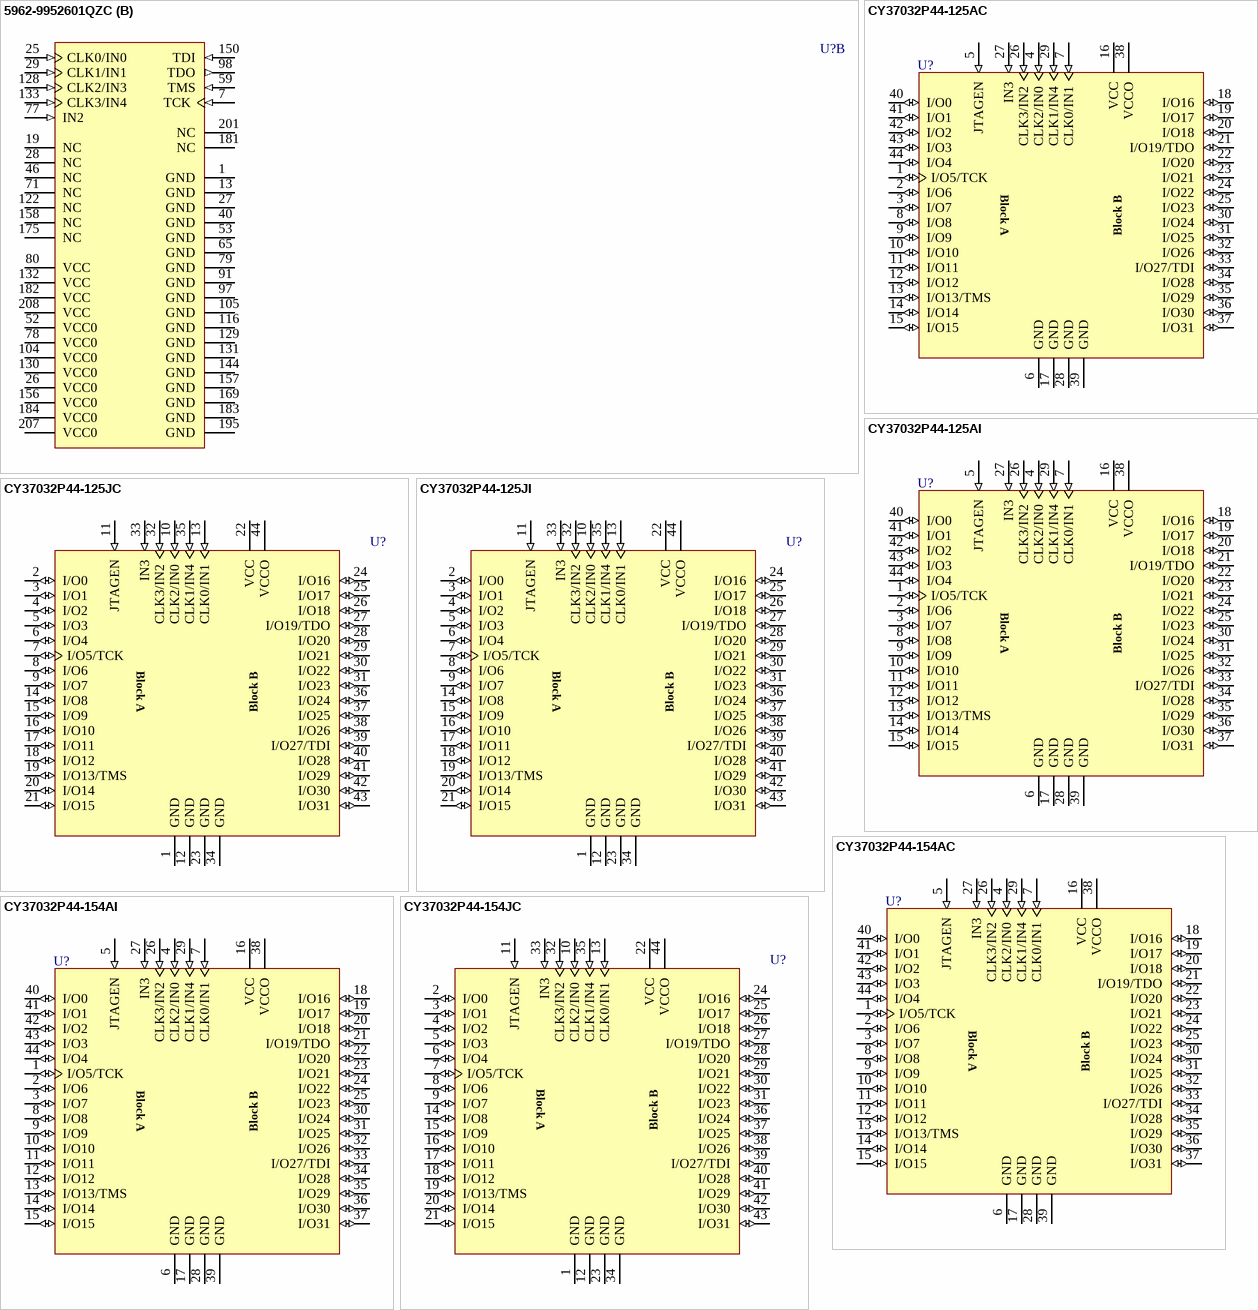
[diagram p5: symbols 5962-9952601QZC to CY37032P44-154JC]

## 5962-9952601QZC
designator U?
Ultra37000 3.3V, ISR High-Performance CPLD; Note: Component Name corresponds to Military Range
footprint U208_N (Shrink QFP, 208-Leads, Body 28x28mm, Pitch 0.5mm, IPC Medium Density)
footprint U208_L (Shrink QFP, 208-Leads, Body 28x28mm, Pitch 0.5mm, IPC High Density)
footprint U208_M (Shrink QFP, 208-Leads, Body 28x28mm, Pitch 0.5mm, IPC Low Density)
3D model U208 (208-Pin Ceramic Cavity Up Shrink Quad Flat Pack 0.5 mm Pitch)
part A pins: 2 I/O20 (io), 3 I/O21 (io), 4 I/O22 (io), 5 I/O23 (io), 6 I/O24 (io), 8 I/O25 (io), 9 I/O26 (io), 10 I/O27 (io), 11 I/O28 (io), 12 I/O29 (io), 14 I/O30 (io), 15 I/O31 (io), 16 I/O32 (io), 17 I/O33 (io), 18 I/O34 (io), 20 I/O35 (io), 21 I/O36 (io), 22 I/O37 (io), 23 I/O38 (io), 24 I/O39 (io), 30 I/O40 (io), 31 I/O41 (io), 32 I/O42 (io), 33 I/O43 (io), 34 I/O44 (io), 35 I/O45 (io), 36 I/O46 (io), 37 I/O47 (io), 38 I/O48 (io), 39 I/O49 (io), 41 I/O50 (io), 42 I/O51 (io), 43 I/O52 (io), 44 I/O53 (io), 45 I/O54 (io), 47 I/O55 (io), 48 I/O56 (io), 49 I/O57 (io), 50 I/O58 (io), 51 I/O59 (io), 54 I/O60 (io), 55 I/O61 (io), 56 I/O62 (io), 57 I/O63 (io), 58 I/O64 (io), 60 I/O65 (io), 61 I/O66 (io), 62 I/O67 (io), 63 I/O68 (io), 64 I/O69 (io), 66 I/O70 (io), 67 I/O71 (io), 68 I/O72 (io), 69 I/O73 (io), 70 I/O74 (io), 72 I/O75 (io), 73 I/O76 (io), 74 I/O77 (io), 75 I/O78 (io), 76 I/O79 (io), 81 I/O80 (io), 82 I/O81 (io), 83 I/O82 (io), 84 I/O83 (io), 85 I/O84 (io), 86 I/O85 (io), 87 I/O86 (io), 88 I/O87 (io), 89 I/O88 (io), 90 I/O89 (io), 92 I/O90 (io), 93 I/O91 (io), 94 I/O92 (io), 95 I/O93 (io), 96 I/O94 (io), 99 I/O95 (io), 100 I/O96 (io), 101 I/O97 (io), 102 I/O98 (io), 103 I/O99 (io), 106 I/O100 (io), 107 I/O101 (io), 108 I/O102 (io), 109 I/O103 (io), 110 I/O104 (io), 111 I/O105 (io), 112 I/O106 (io), 113 I/O107 (io), 114 I/O108 (io), 115 I/O109 (io), 117 I/O110 (io), 118 I/O111 (io), 119 I/O112 (io), 120 I/O113 (io), 121 I/O114 (io), 123 I/O115 (io), 124 I/O116 (io), 125 I/O117 (io), 126 I/O118 (io), 127 I/O119 (io), 134 I/O120 (io), 135 I/O121 (io), 136 I/O122 (io), 137 I/O123 (io), 138 I/O124 (io), 139 I/O125 (io), 140 I/O126 (io), 141 I/O127 (io), 142 I/O128 (io), 143 I/O129 (io), 145 I/O130 (io), 146 I/O131 (io), 147 I/O132 (io), 148 I/O133 (io), 149 I/O134 (io), 151 I/O135 (io), 152 I/O136 (io), 153 I/O137 (io), 154 I/O138 (io), 155 I/O139 (io), 159 I/O140 (io), 160 I/O141 (io), 161 I/O142 (io), 162 I/O143 (io), 163 I/O144 (io), 164 I/O145 (io), 165 I/O146 (io), 166 I/O147 (io), 167 I/O148 (io), 168 I/O149 (io), 170 I/O150 (io), 171 I/O151 (io), 172 I/O152 (io), 173 I/O153 (io), 174 I/O154 (io), 176 I/O155 (io), 177 I/O156 (io), 178 I/O157 (io), 179 I/O158 (io), 180 I/O159 (io), 185 I/O0 (io), 186 I/O1 (io), 187 I/O2 (io), 188 I/O3 (io), 189 I/O4 (io), 190 I/O5 (io), 191 I/O6 (io), 192 I/O7 (io), 193 I/O8 (io), 194 I/O9 (io), 196 I/O10 (io), 197 I/O11 (io), 198 I/O12 (io), 199 I/O13 (io), 200 I/O14 (io), 202 I/O15 (io), 203 I/O16 (io), 204 I/O17 (io), 205 I/O18 (io), 206 I/O19 (io)
part B pins: 1 GND (power), 7 TCK (in), 13 GND (power), 19 NC, 25 CLK0/IN0 (in), 26 VCC0 (power), 27 GND (power), 28 NC, 29 CLK1/IN1 (in), 40 GND (power), 46 NC, 52 VCC0 (power), 53 GND (power), 59 TMS (in), 65 GND (power), 71 NC, 77 IN2 (in), 78 VCC0 (power), 79 GND (power), 80 VCC (power), 91 GND (power), 97 GND (power), 98 TDO (out), 104 VCC0 (power), 105 GND (power), 116 GND (power), 122 NC, 128 CLK2/IN3 (in), 129 GND (power), 130 VCC0 (power), 131 GND (power), 132 VCC (power), 133 CLK3/IN4 (in), 144 GND (power), 150 TDI (in), 156 VCC0 (power), 157 GND (power), 158 NC, 169 GND (power), 175 NC, 181 NC, 182 VCC (power), 183 GND (power), 184 VCC0 (power), 195 GND (power), 201 NC, 207 VCC0 (power), 208 VCC (power)

## CY37032P44-125AC
designator U?
Ultra37000 5V, ISR High-Performance CPLD
footprint A44_N (Thin QFP, 44-Leads, Body 10x10mm, Pitch 0.8mm, IPC Medium Density)
footprint A44_L (Thin QFP, 44-Leads, Body 10x10mm, Pitch 0.8mm, IPC High Density)
footprint A44_M (Thin QFP, 44-Leads, Body 10x10mm, Pitch 0.8mm, IPC Low Density)
3D model CY37032P44-A44 (44-Pin Thin Plastic Quad Flat Pack 0.8 mm Pitch)
pins: 1 I/O5/TCK (io), 2 I/O6 (io), 3 I/O7 (io), 4 CLK2/IN0 (in), 5 JTAGEN (in), 6 GND (power), 7 CLK0/IN1 (in), 8 I/O8 (io), 9 I/O9 (io), 10 I/O10 (io), 11 I/O11 (io), 12 I/O12 (io), 13 I/O13/TMS (io), 14 I/O14 (io), 15 I/O15 (io), 16 VCC (power), 17 GND (power), 18 I/O16 (io), 19 I/O17 (io), 20 I/O18 (io), 21 I/O19/TDO (io), 22 I/O20 (io), 23 I/O21 (io), 24 I/O22 (io), 25 I/O23 (io), 26 CLK3/IN2 (in), 27 IN3 (in), 28 GND (power), 29 CLK1/IN4 (in), 30 I/O24 (io), 31 I/O25 (io), 32 I/O26 (io), 33 I/O27/TDI (io), 34 I/O28 (io), 35 I/O29 (io), 36 I/O30 (io), 37 I/O31 (io), 38 VCCO (power), 39 GND (power), 40 I/O0 (io), 41 I/O1 (io), 42 I/O2 (io), 43 I/O3 (io), 44 I/O4 (io)

## CY37032P44-125AI
designator U?
Ultra37000 5V, ISR High-Performance CPLD
footprint A44_N (Thin QFP, 44-Leads, Body 10x10mm, Pitch 0.8mm, IPC Medium Density)
footprint A44_L (Thin QFP, 44-Leads, Body 10x10mm, Pitch 0.8mm, IPC High Density)
footprint A44_M (Thin QFP, 44-Leads, Body 10x10mm, Pitch 0.8mm, IPC Low Density)
3D model CY37032P44-A44 (44-Pin Thin Plastic Quad Flat Pack 0.8 mm Pitch)
pins: 1 I/O5/TCK (io), 2 I/O6 (io), 3 I/O7 (io), 4 CLK2/IN0 (in), 5 JTAGEN (in), 6 GND (power), 7 CLK0/IN1 (in), 8 I/O8 (io), 9 I/O9 (io), 10 I/O10 (io), 11 I/O11 (io), 12 I/O12 (io), 13 I/O13/TMS (io), 14 I/O14 (io), 15 I/O15 (io), 16 VCC (power), 17 GND (power), 18 I/O16 (io), 19 I/O17 (io), 20 I/O18 (io), 21 I/O19/TDO (io), 22 I/O20 (io), 23 I/O21 (io), 24 I/O22 (io), 25 I/O23 (io), 26 CLK3/IN2 (in), 27 IN3 (in), 28 GND (power), 29 CLK1/IN4 (in), 30 I/O24 (io), 31 I/O25 (io), 32 I/O26 (io), 33 I/O27/TDI (io), 34 I/O28 (io), 35 I/O29 (io), 36 I/O30 (io), 37 I/O31 (io), 38 VCCO (power), 39 GND (power), 40 I/O0 (io), 41 I/O1 (io), 42 I/O2 (io), 43 I/O3 (io), 44 I/O4 (io)

## CY37032P44-125JC
designator U?
Ultra37000 5V, ISR High-Performance CPLD
footprint J67_N (Leaded Chip Carrier, 44-Leads, Body 16.6x16.6mm, Pitch 1.27mm, IPC Medium Density)
footprint J67_L (Leaded Chip Carrier, 44-Leads, Body 16.6x16.6mm, Pitch 1.27mm, IPC High Density)
footprint J67_M (Leaded Chip Carrier, 44-Leads, Body 16.6x16.6mm, Pitch 1.27mm, IPC Low Density)
3D model CY37032P44-J67 (44-Pin Plastic Leaded Chip Carrier 1.27 mm Pitch)
pins: 1 GND (power), 2 I/O0 (io), 3 I/O1 (io), 4 I/O2 (io), 5 I/O3 (io), 6 I/O4 (io), 7 I/O5/TCK (io), 8 I/O6 (io), 9 I/O7 (io), 10 CLK2/IN0 (in), 11 JTAGEN (in), 12 GND (power), 13 CLK0/IN1 (in), 14 I/O8 (io), 15 I/O9 (io), 16 I/O10 (io), 17 I/O11 (io), 18 I/O12 (io), 19 I/O13/TMS (io), 20 I/O14 (io), 21 I/O15 (io), 22 VCC (power), 23 GND (power), 24 I/O16 (io), 25 I/O17 (io), 26 I/O18 (io), 27 I/O19/TDO (io), 28 I/O20 (io), 29 I/O21 (io), 30 I/O22 (io), 31 I/O23 (io), 32 CLK3/IN2 (in), 33 IN3 (in), 34 GND (power), 35 CLK1/IN4 (in), 36 I/O24 (io), 37 I/O25 (io), 38 I/O26 (io), 39 I/O27/TDI (io), 40 I/O28 (io), 41 I/O29 (io), 42 I/O30 (io), 43 I/O31 (io), 44 VCCO (power)

## CY37032P44-125JI
designator U?
Ultra37000 5V, ISR High-Performance CPLD
footprint J67_N (Leaded Chip Carrier, 44-Leads, Body 16.6x16.6mm, Pitch 1.27mm, IPC Medium Density)
footprint J67_L (Leaded Chip Carrier, 44-Leads, Body 16.6x16.6mm, Pitch 1.27mm, IPC High Density)
footprint J67_M (Leaded Chip Carrier, 44-Leads, Body 16.6x16.6mm, Pitch 1.27mm, IPC Low Density)
3D model CY37032P44-J67 (44-Pin Plastic Leaded Chip Carrier 1.27 mm Pitch)
pins: 1 GND (power), 2 I/O0 (io), 3 I/O1 (io), 4 I/O2 (io), 5 I/O3 (io), 6 I/O4 (io), 7 I/O5/TCK (io), 8 I/O6 (io), 9 I/O7 (io), 10 CLK2/IN0 (in), 11 JTAGEN (in), 12 GND (power), 13 CLK0/IN1 (in), 14 I/O8 (io), 15 I/O9 (io), 16 I/O10 (io), 17 I/O11 (io), 18 I/O12 (io), 19 I/O13/TMS (io), 20 I/O14 (io), 21 I/O15 (io), 22 VCC (power), 23 GND (power), 24 I/O16 (io), 25 I/O17 (io), 26 I/O18 (io), 27 I/O19/TDO (io), 28 I/O20 (io), 29 I/O21 (io), 30 I/O22 (io), 31 I/O23 (io), 32 CLK3/IN2 (in), 33 IN3 (in), 34 GND (power), 35 CLK1/IN4 (in), 36 I/O24 (io), 37 I/O25 (io), 38 I/O26 (io), 39 I/O27/TDI (io), 40 I/O28 (io), 41 I/O29 (io), 42 I/O30 (io), 43 I/O31 (io), 44 VCCO (power)

## CY37032P44-154AC
designator U?
Ultra37000 5V, ISR High-Performance CPLD
footprint A44_N (Thin QFP, 44-Leads, Body 10x10mm, Pitch 0.8mm, IPC Medium Density)
footprint A44_L (Thin QFP, 44-Leads, Body 10x10mm, Pitch 0.8mm, IPC High Density)
footprint A44_M (Thin QFP, 44-Leads, Body 10x10mm, Pitch 0.8mm, IPC Low Density)
3D model CY37032P44-A44 (44-Pin Thin Plastic Quad Flat Pack 0.8 mm Pitch)
pins: 1 I/O5/TCK (io), 2 I/O6 (io), 3 I/O7 (io), 4 CLK2/IN0 (in), 5 JTAGEN (in), 6 GND (power), 7 CLK0/IN1 (in), 8 I/O8 (io), 9 I/O9 (io), 10 I/O10 (io), 11 I/O11 (io), 12 I/O12 (io), 13 I/O13/TMS (io), 14 I/O14 (io), 15 I/O15 (io), 16 VCC (power), 17 GND (power), 18 I/O16 (io), 19 I/O17 (io), 20 I/O18 (io), 21 I/O19/TDO (io), 22 I/O20 (io), 23 I/O21 (io), 24 I/O22 (io), 25 I/O23 (io), 26 CLK3/IN2 (in), 27 IN3 (in), 28 GND (power), 29 CLK1/IN4 (in), 30 I/O24 (io), 31 I/O25 (io), 32 I/O26 (io), 33 I/O27/TDI (io), 34 I/O28 (io), 35 I/O29 (io), 36 I/O30 (io), 37 I/O31 (io), 38 VCCO (power), 39 GND (power), 40 I/O0 (io), 41 I/O1 (io), 42 I/O2 (io), 43 I/O3 (io), 44 I/O4 (io)

## CY37032P44-154AI
designator U?
Ultra37000 5V, ISR High-Performance CPLD
footprint A44_N (Thin QFP, 44-Leads, Body 10x10mm, Pitch 0.8mm, IPC Medium Density)
footprint A44_L (Thin QFP, 44-Leads, Body 10x10mm, Pitch 0.8mm, IPC High Density)
footprint A44_M (Thin QFP, 44-Leads, Body 10x10mm, Pitch 0.8mm, IPC Low Density)
3D model CY37032P44-A44 (44-Pin Thin Plastic Quad Flat Pack 0.8 mm Pitch)
pins: 1 I/O5/TCK (io), 2 I/O6 (io), 3 I/O7 (io), 4 CLK2/IN0 (in), 5 JTAGEN (in), 6 GND (power), 7 CLK0/IN1 (in), 8 I/O8 (io), 9 I/O9 (io), 10 I/O10 (io), 11 I/O11 (io), 12 I/O12 (io), 13 I/O13/TMS (io), 14 I/O14 (io), 15 I/O15 (io), 16 VCC (power), 17 GND (power), 18 I/O16 (io), 19 I/O17 (io), 20 I/O18 (io), 21 I/O19/TDO (io), 22 I/O20 (io), 23 I/O21 (io), 24 I/O22 (io), 25 I/O23 (io), 26 CLK3/IN2 (in), 27 IN3 (in), 28 GND (power), 29 CLK1/IN4 (in), 30 I/O24 (io), 31 I/O25 (io), 32 I/O26 (io), 33 I/O27/TDI (io), 34 I/O28 (io), 35 I/O29 (io), 36 I/O30 (io), 37 I/O31 (io), 38 VCCO (power), 39 GND (power), 40 I/O0 (io), 41 I/O1 (io), 42 I/O2 (io), 43 I/O3 (io), 44 I/O4 (io)

## CY37032P44-154JC
designator U?
Ultra37000 5V, ISR High-Performance CPLD
footprint J67_N (Leaded Chip Carrier, 44-Leads, Body 16.6x16.6mm, Pitch 1.27mm, IPC Medium Density)
footprint J67_L (Leaded Chip Carrier, 44-Leads, Body 16.6x16.6mm, Pitch 1.27mm, IPC High Density)
footprint J67_M (Leaded Chip Carrier, 44-Leads, Body 16.6x16.6mm, Pitch 1.27mm, IPC Low Density)
3D model CY37032P44-J67 (44-Pin Plastic Leaded Chip Carrier 1.27 mm Pitch)
pins: 1 GND (power), 2 I/O0 (io), 3 I/O1 (io), 4 I/O2 (io), 5 I/O3 (io), 6 I/O4 (io), 7 I/O5/TCK (io), 8 I/O6 (io), 9 I/O7 (io), 10 CLK2/IN0 (in), 11 JTAGEN (in), 12 GND (power), 13 CLK0/IN1 (in), 14 I/O8 (io), 15 I/O9 (io), 16 I/O10 (io), 17 I/O11 (io), 18 I/O12 (io), 19 I/O13/TMS (io), 20 I/O14 (io), 21 I/O15 (io), 22 VCC (power), 23 GND (power), 24 I/O16 (io), 25 I/O17 (io), 26 I/O18 (io), 27 I/O19/TDO (io), 28 I/O20 (io), 29 I/O21 (io), 30 I/O22 (io), 31 I/O23 (io), 32 CLK3/IN2 (in), 33 IN3 (in), 34 GND (power), 35 CLK1/IN4 (in), 36 I/O24 (io), 37 I/O25 (io), 38 I/O26 (io), 39 I/O27/TDI (io), 40 I/O28 (io), 41 I/O29 (io), 42 I/O30 (io), 43 I/O31 (io), 44 VCCO (power)

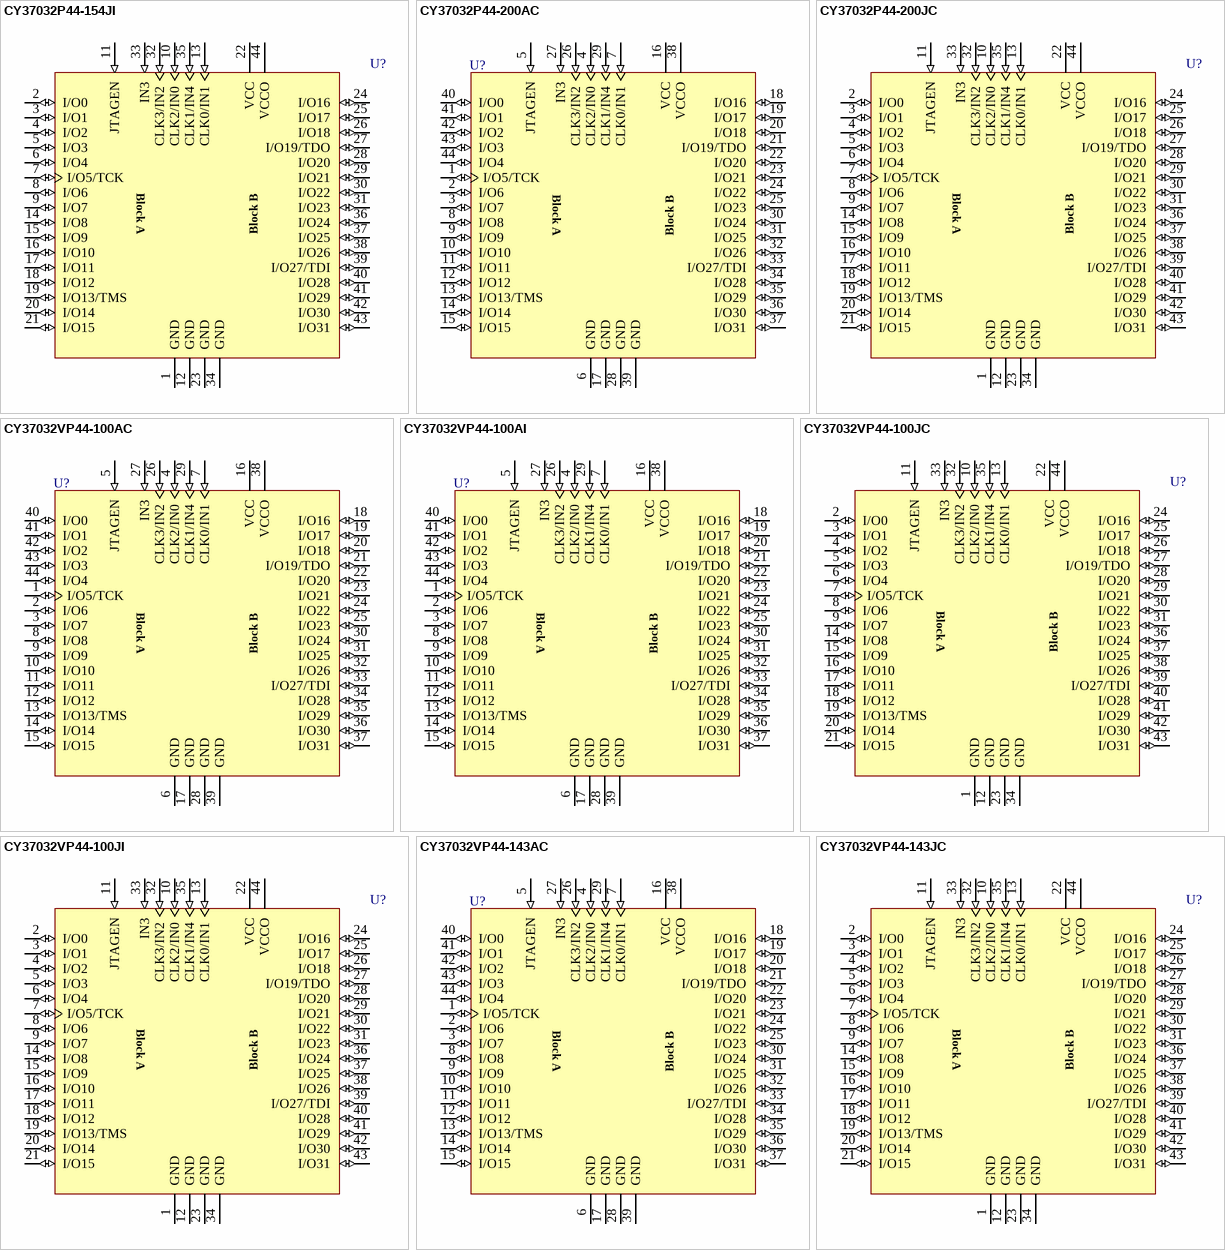
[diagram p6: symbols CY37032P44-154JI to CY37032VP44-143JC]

## CY37032P44-154JI
designator U?
Ultra37000 5V, ISR High-Performance CPLD
footprint J67_N (Leaded Chip Carrier, 44-Leads, Body 16.6x16.6mm, Pitch 1.27mm, IPC Medium Density)
footprint J67_L (Leaded Chip Carrier, 44-Leads, Body 16.6x16.6mm, Pitch 1.27mm, IPC High Density)
footprint J67_M (Leaded Chip Carrier, 44-Leads, Body 16.6x16.6mm, Pitch 1.27mm, IPC Low Density)
3D model CY37032P44-J67 (44-Pin Plastic Leaded Chip Carrier 1.27 mm Pitch)
pins: 1 GND (power), 2 I/O0 (io), 3 I/O1 (io), 4 I/O2 (io), 5 I/O3 (io), 6 I/O4 (io), 7 I/O5/TCK (io), 8 I/O6 (io), 9 I/O7 (io), 10 CLK2/IN0 (in), 11 JTAGEN (in), 12 GND (power), 13 CLK0/IN1 (in), 14 I/O8 (io), 15 I/O9 (io), 16 I/O10 (io), 17 I/O11 (io), 18 I/O12 (io), 19 I/O13/TMS (io), 20 I/O14 (io), 21 I/O15 (io), 22 VCC (power), 23 GND (power), 24 I/O16 (io), 25 I/O17 (io), 26 I/O18 (io), 27 I/O19/TDO (io), 28 I/O20 (io), 29 I/O21 (io), 30 I/O22 (io), 31 I/O23 (io), 32 CLK3/IN2 (in), 33 IN3 (in), 34 GND (power), 35 CLK1/IN4 (in), 36 I/O24 (io), 37 I/O25 (io), 38 I/O26 (io), 39 I/O27/TDI (io), 40 I/O28 (io), 41 I/O29 (io), 42 I/O30 (io), 43 I/O31 (io), 44 VCCO (power)

## CY37032P44-200AC
designator U?
Ultra37000 5V, ISR High-Performance CPLD
footprint A44_N (Thin QFP, 44-Leads, Body 10x10mm, Pitch 0.8mm, IPC Medium Density)
footprint A44_L (Thin QFP, 44-Leads, Body 10x10mm, Pitch 0.8mm, IPC High Density)
footprint A44_M (Thin QFP, 44-Leads, Body 10x10mm, Pitch 0.8mm, IPC Low Density)
3D model CY37032P44-A44 (44-Pin Thin Plastic Quad Flat Pack 0.8 mm Pitch)
pins: 1 I/O5/TCK (io), 2 I/O6 (io), 3 I/O7 (io), 4 CLK2/IN0 (in), 5 JTAGEN (in), 6 GND (power), 7 CLK0/IN1 (in), 8 I/O8 (io), 9 I/O9 (io), 10 I/O10 (io), 11 I/O11 (io), 12 I/O12 (io), 13 I/O13/TMS (io), 14 I/O14 (io), 15 I/O15 (io), 16 VCC (power), 17 GND (power), 18 I/O16 (io), 19 I/O17 (io), 20 I/O18 (io), 21 I/O19/TDO (io), 22 I/O20 (io), 23 I/O21 (io), 24 I/O22 (io), 25 I/O23 (io), 26 CLK3/IN2 (in), 27 IN3 (in), 28 GND (power), 29 CLK1/IN4 (in), 30 I/O24 (io), 31 I/O25 (io), 32 I/O26 (io), 33 I/O27/TDI (io), 34 I/O28 (io), 35 I/O29 (io), 36 I/O30 (io), 37 I/O31 (io), 38 VCCO (power), 39 GND (power), 40 I/O0 (io), 41 I/O1 (io), 42 I/O2 (io), 43 I/O3 (io), 44 I/O4 (io)

## CY37032P44-200JC
designator U?
Ultra37000 5V, ISR High-Performance CPLD
footprint J67_N (Leaded Chip Carrier, 44-Leads, Body 16.6x16.6mm, Pitch 1.27mm, IPC Medium Density)
footprint J67_L (Leaded Chip Carrier, 44-Leads, Body 16.6x16.6mm, Pitch 1.27mm, IPC High Density)
footprint J67_M (Leaded Chip Carrier, 44-Leads, Body 16.6x16.6mm, Pitch 1.27mm, IPC Low Density)
3D model CY37032P44-J67 (44-Pin Plastic Leaded Chip Carrier 1.27 mm Pitch)
pins: 1 GND (power), 2 I/O0 (io), 3 I/O1 (io), 4 I/O2 (io), 5 I/O3 (io), 6 I/O4 (io), 7 I/O5/TCK (io), 8 I/O6 (io), 9 I/O7 (io), 10 CLK2/IN0 (in), 11 JTAGEN (in), 12 GND (power), 13 CLK0/IN1 (in), 14 I/O8 (io), 15 I/O9 (io), 16 I/O10 (io), 17 I/O11 (io), 18 I/O12 (io), 19 I/O13/TMS (io), 20 I/O14 (io), 21 I/O15 (io), 22 VCC (power), 23 GND (power), 24 I/O16 (io), 25 I/O17 (io), 26 I/O18 (io), 27 I/O19/TDO (io), 28 I/O20 (io), 29 I/O21 (io), 30 I/O22 (io), 31 I/O23 (io), 32 CLK3/IN2 (in), 33 IN3 (in), 34 GND (power), 35 CLK1/IN4 (in), 36 I/O24 (io), 37 I/O25 (io), 38 I/O26 (io), 39 I/O27/TDI (io), 40 I/O28 (io), 41 I/O29 (io), 42 I/O30 (io), 43 I/O31 (io), 44 VCCO (power)

## CY37032VP44-100AC
designator U?
Ultra37000 3.3V, ISR High-Performance CPLD
footprint A44_N (Thin QFP, 44-Leads, Body 10x10mm, Pitch 0.8mm, IPC Medium Density)
footprint A44_L (Thin QFP, 44-Leads, Body 10x10mm, Pitch 0.8mm, IPC High Density)
footprint A44_M (Thin QFP, 44-Leads, Body 10x10mm, Pitch 0.8mm, IPC Low Density)
3D model CY37032VP44-A44 (44-Pin Thin Plastic Quad Flat Pack 0.8 mm Pitch)
pins: 1 I/O5/TCK (io), 2 I/O6 (io), 3 I/O7 (io), 4 CLK2/IN0 (in), 5 JTAGEN (in), 6 GND (power), 7 CLK0/IN1 (in), 8 I/O8 (io), 9 I/O9 (io), 10 I/O10 (io), 11 I/O11 (io), 12 I/O12 (io), 13 I/O13/TMS (io), 14 I/O14 (io), 15 I/O15 (io), 16 VCC (power), 17 GND (power), 18 I/O16 (io), 19 I/O17 (io), 20 I/O18 (io), 21 I/O19/TDO (io), 22 I/O20 (io), 23 I/O21 (io), 24 I/O22 (io), 25 I/O23 (io), 26 CLK3/IN2 (in), 27 IN3 (in), 28 GND (power), 29 CLK1/IN4 (in), 30 I/O24 (io), 31 I/O25 (io), 32 I/O26 (io), 33 I/O27/TDI (io), 34 I/O28 (io), 35 I/O29 (io), 36 I/O30 (io), 37 I/O31 (io), 38 VCCO (power), 39 GND (power), 40 I/O0 (io), 41 I/O1 (io), 42 I/O2 (io), 43 I/O3 (io), 44 I/O4 (io)

## CY37032VP44-100AI
designator U?
Ultra37000 3.3V, ISR High-Performance CPLD
footprint A44_N (Thin QFP, 44-Leads, Body 10x10mm, Pitch 0.8mm, IPC Medium Density)
footprint A44_L (Thin QFP, 44-Leads, Body 10x10mm, Pitch 0.8mm, IPC High Density)
footprint A44_M (Thin QFP, 44-Leads, Body 10x10mm, Pitch 0.8mm, IPC Low Density)
3D model CY37032VP44-A44 (44-Pin Thin Plastic Quad Flat Pack 0.8 mm Pitch)
pins: 1 I/O5/TCK (io), 2 I/O6 (io), 3 I/O7 (io), 4 CLK2/IN0 (in), 5 JTAGEN (in), 6 GND (power), 7 CLK0/IN1 (in), 8 I/O8 (io), 9 I/O9 (io), 10 I/O10 (io), 11 I/O11 (io), 12 I/O12 (io), 13 I/O13/TMS (io), 14 I/O14 (io), 15 I/O15 (io), 16 VCC (power), 17 GND (power), 18 I/O16 (io), 19 I/O17 (io), 20 I/O18 (io), 21 I/O19/TDO (io), 22 I/O20 (io), 23 I/O21 (io), 24 I/O22 (io), 25 I/O23 (io), 26 CLK3/IN2 (in), 27 IN3 (in), 28 GND (power), 29 CLK1/IN4 (in), 30 I/O24 (io), 31 I/O25 (io), 32 I/O26 (io), 33 I/O27/TDI (io), 34 I/O28 (io), 35 I/O29 (io), 36 I/O30 (io), 37 I/O31 (io), 38 VCCO (power), 39 GND (power), 40 I/O0 (io), 41 I/O1 (io), 42 I/O2 (io), 43 I/O3 (io), 44 I/O4 (io)

## CY37032VP44-100JC
designator U?
Ultra37000 3.3V, ISR High-Performance CPLD; ComponentAvailability: Obsolete
footprint J67_N (Leaded Chip Carrier, 44-Leads, Body 16.6x16.6mm, Pitch 1.27mm, IPC Medium Density)
footprint J67_L (Leaded Chip Carrier, 44-Leads, Body 16.6x16.6mm, Pitch 1.27mm, IPC High Density)
footprint J67_M (Leaded Chip Carrier, 44-Leads, Body 16.6x16.6mm, Pitch 1.27mm, IPC Low Density)
3D model CY37032VP44-J67 (44-Pin Plastic Leaded Chip Carrier 1.27 mm Pitch)
pins: 1 GND (power), 2 I/O0 (io), 3 I/O1 (io), 4 I/O2 (io), 5 I/O3 (io), 6 I/O4 (io), 7 I/O5/TCK (io), 8 I/O6 (io), 9 I/O7 (io), 10 CLK2/IN0 (in), 11 JTAGEN (in), 12 GND (power), 13 CLK0/IN1 (in), 14 I/O8 (io), 15 I/O9 (io), 16 I/O10 (io), 17 I/O11 (io), 18 I/O12 (io), 19 I/O13/TMS (io), 20 I/O14 (io), 21 I/O15 (io), 22 VCC (power), 23 GND (power), 24 I/O16 (io), 25 I/O17 (io), 26 I/O18 (io), 27 I/O19/TDO (io), 28 I/O20 (io), 29 I/O21 (io), 30 I/O22 (io), 31 I/O23 (io), 32 CLK3/IN2 (in), 33 IN3 (in), 34 GND (power), 35 CLK1/IN4 (in), 36 I/O24 (io), 37 I/O25 (io), 38 I/O26 (io), 39 I/O27/TDI (io), 40 I/O28 (io), 41 I/O29 (io), 42 I/O30 (io), 43 I/O31 (io), 44 VCCO (power)

## CY37032VP44-100JI
designator U?
Ultra37000 3.3V, ISR High-Performance CPLD; ComponentAvailability: Obsolete
footprint J67_N (Leaded Chip Carrier, 44-Leads, Body 16.6x16.6mm, Pitch 1.27mm, IPC Medium Density)
footprint J67_L (Leaded Chip Carrier, 44-Leads, Body 16.6x16.6mm, Pitch 1.27mm, IPC High Density)
footprint J67_M (Leaded Chip Carrier, 44-Leads, Body 16.6x16.6mm, Pitch 1.27mm, IPC Low Density)
3D model CY37032VP44-J67 (44-Pin Plastic Leaded Chip Carrier 1.27 mm Pitch)
pins: 1 GND (power), 2 I/O0 (io), 3 I/O1 (io), 4 I/O2 (io), 5 I/O3 (io), 6 I/O4 (io), 7 I/O5/TCK (io), 8 I/O6 (io), 9 I/O7 (io), 10 CLK2/IN0 (in), 11 JTAGEN (in), 12 GND (power), 13 CLK0/IN1 (in), 14 I/O8 (io), 15 I/O9 (io), 16 I/O10 (io), 17 I/O11 (io), 18 I/O12 (io), 19 I/O13/TMS (io), 20 I/O14 (io), 21 I/O15 (io), 22 VCC (power), 23 GND (power), 24 I/O16 (io), 25 I/O17 (io), 26 I/O18 (io), 27 I/O19/TDO (io), 28 I/O20 (io), 29 I/O21 (io), 30 I/O22 (io), 31 I/O23 (io), 32 CLK3/IN2 (in), 33 IN3 (in), 34 GND (power), 35 CLK1/IN4 (in), 36 I/O24 (io), 37 I/O25 (io), 38 I/O26 (io), 39 I/O27/TDI (io), 40 I/O28 (io), 41 I/O29 (io), 42 I/O30 (io), 43 I/O31 (io), 44 VCCO (power)

## CY37032VP44-143AC
designator U?
Ultra37000 3.3V, ISR High-Performance CPLD
footprint A44_N (Thin QFP, 44-Leads, Body 10x10mm, Pitch 0.8mm, IPC Medium Density)
footprint A44_L (Thin QFP, 44-Leads, Body 10x10mm, Pitch 0.8mm, IPC High Density)
footprint A44_M (Thin QFP, 44-Leads, Body 10x10mm, Pitch 0.8mm, IPC Low Density)
3D model CY37032VP44-A44 (44-Pin Thin Plastic Quad Flat Pack 0.8 mm Pitch)
pins: 1 I/O5/TCK (io), 2 I/O6 (io), 3 I/O7 (io), 4 CLK2/IN0 (in), 5 JTAGEN (in), 6 GND (power), 7 CLK0/IN1 (in), 8 I/O8 (io), 9 I/O9 (io), 10 I/O10 (io), 11 I/O11 (io), 12 I/O12 (io), 13 I/O13/TMS (io), 14 I/O14 (io), 15 I/O15 (io), 16 VCC (power), 17 GND (power), 18 I/O16 (io), 19 I/O17 (io), 20 I/O18 (io), 21 I/O19/TDO (io), 22 I/O20 (io), 23 I/O21 (io), 24 I/O22 (io), 25 I/O23 (io), 26 CLK3/IN2 (in), 27 IN3 (in), 28 GND (power), 29 CLK1/IN4 (in), 30 I/O24 (io), 31 I/O25 (io), 32 I/O26 (io), 33 I/O27/TDI (io), 34 I/O28 (io), 35 I/O29 (io), 36 I/O30 (io), 37 I/O31 (io), 38 VCCO (power), 39 GND (power), 40 I/O0 (io), 41 I/O1 (io), 42 I/O2 (io), 43 I/O3 (io), 44 I/O4 (io)

## CY37032VP44-143JC
designator U?
Ultra37000 3.3V, ISR High-Performance CPLD; ComponentAvailability: Obsolete
footprint J67_N (Leaded Chip Carrier, 44-Leads, Body 16.6x16.6mm, Pitch 1.27mm, IPC Medium Density)
footprint J67_L (Leaded Chip Carrier, 44-Leads, Body 16.6x16.6mm, Pitch 1.27mm, IPC High Density)
footprint J67_M (Leaded Chip Carrier, 44-Leads, Body 16.6x16.6mm, Pitch 1.27mm, IPC Low Density)
3D model CY37032VP44-J67 (44-Pin Plastic Leaded Chip Carrier 1.27 mm Pitch)
pins: 1 GND (power), 2 I/O0 (io), 3 I/O1 (io), 4 I/O2 (io), 5 I/O3 (io), 6 I/O4 (io), 7 I/O5/TCK (io), 8 I/O6 (io), 9 I/O7 (io), 10 CLK2/IN0 (in), 11 JTAGEN (in), 12 GND (power), 13 CLK0/IN1 (in), 14 I/O8 (io), 15 I/O9 (io), 16 I/O10 (io), 17 I/O11 (io), 18 I/O12 (io), 19 I/O13/TMS (io), 20 I/O14 (io), 21 I/O15 (io), 22 VCC (power), 23 GND (power), 24 I/O16 (io), 25 I/O17 (io), 26 I/O18 (io), 27 I/O19/TDO (io), 28 I/O20 (io), 29 I/O21 (io), 30 I/O22 (io), 31 I/O23 (io), 32 CLK3/IN2 (in), 33 IN3 (in), 34 GND (power), 35 CLK1/IN4 (in), 36 I/O24 (io), 37 I/O25 (io), 38 I/O26 (io), 39 I/O27/TDI (io), 40 I/O28 (io), 41 I/O29 (io), 42 I/O30 (io), 43 I/O31 (io), 44 VCCO (power)

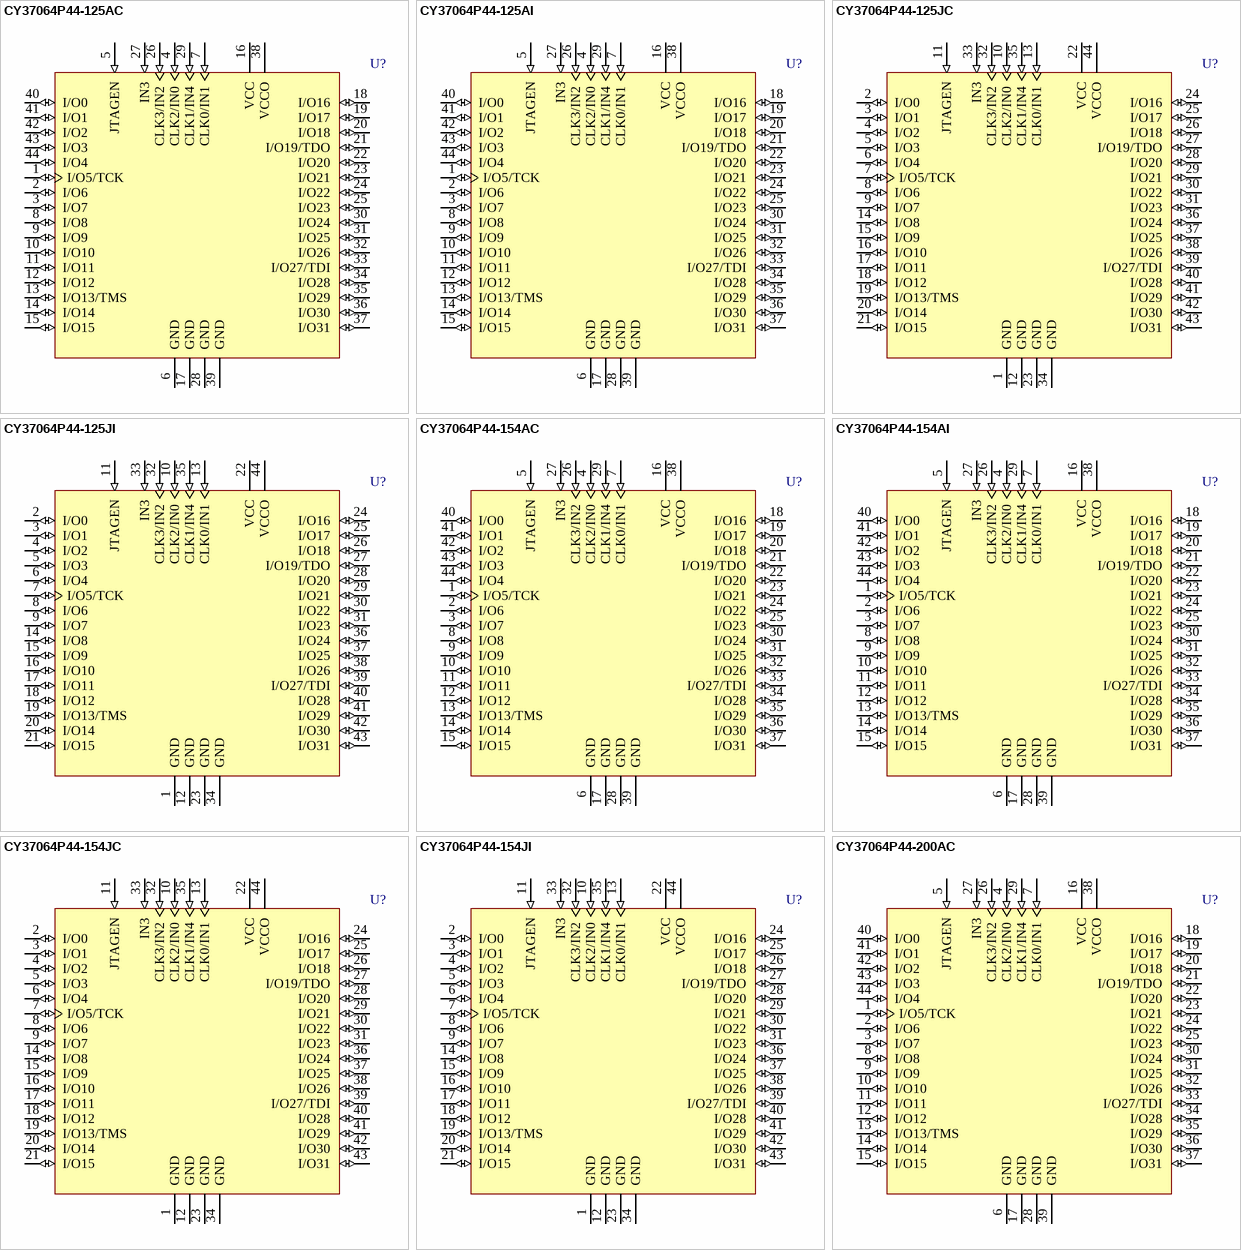
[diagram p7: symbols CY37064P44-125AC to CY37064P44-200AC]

## CY37064P44-125AC
designator U?
Ultra37000 5V, ISR High-Performance CPLD
footprint A44_N (Thin QFP, 44-Leads, Body 10x10mm, Pitch 0.8mm, IPC Medium Density)
footprint A44_L (Thin QFP, 44-Leads, Body 10x10mm, Pitch 0.8mm, IPC High Density)
footprint A44_M (Thin QFP, 44-Leads, Body 10x10mm, Pitch 0.8mm, IPC Low Density)
3D model CY37064P44-A44 (44-Pin Thin Plastic Quad Flat Pack 0.8 mm Pitch)
pins: 1 I/O5/TCK (io), 2 I/O6 (io), 3 I/O7 (io), 4 CLK2/IN0 (in), 5 JTAGEN (in), 6 GND (power), 7 CLK0/IN1 (in), 8 I/O8 (io), 9 I/O9 (io), 10 I/O10 (io), 11 I/O11 (io), 12 I/O12 (io), 13 I/O13/TMS (io), 14 I/O14 (io), 15 I/O15 (io), 16 VCC (power), 17 GND (power), 18 I/O16 (io), 19 I/O17 (io), 20 I/O18 (io), 21 I/O19/TDO (io), 22 I/O20 (io), 23 I/O21 (io), 24 I/O22 (io), 25 I/O23 (io), 26 CLK3/IN2 (in), 27 IN3 (in), 28 GND (power), 29 CLK1/IN4 (in), 30 I/O24 (io), 31 I/O25 (io), 32 I/O26 (io), 33 I/O27/TDI (io), 34 I/O28 (io), 35 I/O29 (io), 36 I/O30 (io), 37 I/O31 (io), 38 VCCO (power), 39 GND (power), 40 I/O0 (io), 41 I/O1 (io), 42 I/O2 (io), 43 I/O3 (io), 44 I/O4 (io)

## CY37064P44-125AI
designator U?
Ultra37000 5V, ISR High-Performance CPLD
footprint A44_N (Thin QFP, 44-Leads, Body 10x10mm, Pitch 0.8mm, IPC Medium Density)
footprint A44_L (Thin QFP, 44-Leads, Body 10x10mm, Pitch 0.8mm, IPC High Density)
footprint A44_M (Thin QFP, 44-Leads, Body 10x10mm, Pitch 0.8mm, IPC Low Density)
3D model CY37064P44-A44 (44-Pin Thin Plastic Quad Flat Pack 0.8 mm Pitch)
pins: 1 I/O5/TCK (io), 2 I/O6 (io), 3 I/O7 (io), 4 CLK2/IN0 (in), 5 JTAGEN (in), 6 GND (power), 7 CLK0/IN1 (in), 8 I/O8 (io), 9 I/O9 (io), 10 I/O10 (io), 11 I/O11 (io), 12 I/O12 (io), 13 I/O13/TMS (io), 14 I/O14 (io), 15 I/O15 (io), 16 VCC (power), 17 GND (power), 18 I/O16 (io), 19 I/O17 (io), 20 I/O18 (io), 21 I/O19/TDO (io), 22 I/O20 (io), 23 I/O21 (io), 24 I/O22 (io), 25 I/O23 (io), 26 CLK3/IN2 (in), 27 IN3 (in), 28 GND (power), 29 CLK1/IN4 (in), 30 I/O24 (io), 31 I/O25 (io), 32 I/O26 (io), 33 I/O27/TDI (io), 34 I/O28 (io), 35 I/O29 (io), 36 I/O30 (io), 37 I/O31 (io), 38 VCCO (power), 39 GND (power), 40 I/O0 (io), 41 I/O1 (io), 42 I/O2 (io), 43 I/O3 (io), 44 I/O4 (io)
